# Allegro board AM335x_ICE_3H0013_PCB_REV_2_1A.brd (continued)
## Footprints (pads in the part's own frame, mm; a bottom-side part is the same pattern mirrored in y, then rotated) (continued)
CNRAPC722
  round 4.191 hole 3.556: 1(0,0)
  round 3.683 hole 3.048: 2(4.801,-2.997) 3(0,-6.248)
CNRJ45-1X1WLED
  round 3.2 hole 3.2 unplated: (-1.27,-6.35) (10.16,-6.35)
  rect 1.525x1.525 hole 0.89: 1(0,0)
  round 1.525 hole 0.89: 2(1.27,2.54) 3(2.54,0) 4(3.81,2.54) 5(5.08,0) 6(6.35,2.54) 7(7.62,0) 8(8.89,2.54)
  round 1.655 hole 1.02: 9(11.17,-8.89) 10(11.17,-10.92) 11(-2.28,-8.89) 12(-2.28,-10.92)
  round 2.337 hole 1.702: 13(-3.43,-3.3) 14(12.32,-3.3)
CON14_P5MM_3P75X9P5SMD
  rect 1.016x1.016 smd: (-1.025,-4.475) (-1.025,4.475)
  rect 0.95x0.305 smd: 1(1.675,3.25) 2(1.675,2.75) 3(1.675,2.25) 4(1.675,1.75) 5(1.675,1.25) 6(1.675,0.75) 7(1.675,0.25) 8(1.675,-0.25) 9(1.675,-0.75) 10(1.675,-1.25) 11(1.675,-1.75) 12(1.675,-2.25) 13(1.675,-2.75) 14(1.675,-3.25)
CONN_OSTTC02
  round 1.778 hole 1.27: 1(0,0) 2(5.08,0)
DA2304
  rect 1.7x1.6 smd: 1(-5.4,3) 2(-5.4,1) 3(-5.4,-1) 4(-5.4,-3) 5(5.4,-3) 6(5.4,-1) 7(5.4,1) 8(5.4,3)
DBV5
  rect 0.635x1.27 smd: 1(-0.95,-1.25) 2(0,-1.25) 3(0.95,-1.25) 4(0.95,1.25) 5(-0.95,1.25)
DCK5
  rect 0.46x0.66 smd: 1(-0.65,-0.991) 2(0,-0.991) 3(0.65,-0.991) 4(0.65,0.991) 5(-0.65,0.991)
DO157LS_116X220SMA
  rect 2.5x1.75 smd: 1(-2,0) 2(2,0)
DRCPSO_10PIN
  rect 0.8x0.25 smd: 1(-1.5,1) 2(-1.5,0.5) 3(-1.5,0) 4(-1.5,-0.5) 5(-1.5,-1) 6(1.5,-1) 7(1.5,-0.5) 8(1.5,0) 9(1.5,0.5) 10(1.5,1)
  custom 0.412x0.412 smd: 11(0,0)
EXB-2HV330JV
  rect 0.305x0.711 smd: 1(-1.75,-0.8) 2(-1.25,-0.8) 3(-0.75,-0.8) 4(-0.25,-0.8) 5(0.25,-0.8) 6(0.75,-0.8) 7(1.25,-0.8) 8(1.75,-0.8) 9(1.75,0.8) 10(1.25,0.8) 11(0.75,0.8) 12(0.25,0.8) 13(-0.25,0.8) 14(-0.75,0.8) 15(-1.25,0.8) 16(-1.75,0.8)
HDR2X9VER_335M
  rect 1.524x1.524 hole 0.889: 1(0,0)
  round 1.524 hole 0.889: 2(0,2.54) 3(2.54,0) 4(2.54,2.54) 5(5.08,0) 6(5.08,2.54) 7(7.62,0) 8(7.62,2.54) 9(10.16,0) 10(10.16,2.54) 11(12.7,0) 12(12.7,2.54) 13(15.24,0) 14(15.24,2.54) 15(17.78,0) 16(17.78,2.54) 17(20.32,0) 18(20.32,2.54)
HDR2X15-344M
  rect 1.655x1.655 hole 1.02: 1(0,0)
  round 1.655 hole 1.02: 2(0,2.54) 3(2.54,0) 4(2.54,2.54) 5(5.08,0) 6(5.08,2.54) 7(7.62,0) 8(7.62,2.54) 9(10.16,0) 10(10.16,2.54) 11(12.7,0) 12(12.7,2.54) 13(15.24,0) 14(15.24,2.54) 15(17.78,0) 16(17.78,2.54) 17(20.32,0) 18(20.32,2.54) 19(22.86,0) 20(22.86,2.54) 21(25.4,0) 22(25.4,2.54) 23(27.94,0) 24(27.94,2.54) 25(30.48,0) 26(30.48,2.54) 27(33.02,0) 28(33.02,2.54) 29(35.56,0) 30(35.56,2.54)
HDR2X20-335M
  rect 1.524x1.524 hole 0.889: 1(0,0)
  round 1.524 hole 0.889: 2(0,2.54) 3(2.54,0) 4(2.54,2.54) 5(5.08,0) 6(5.08,2.54) 7(7.62,0) 8(7.62,2.54) 9(10.16,0) 10(10.16,2.54) 11(12.7,0) 12(12.7,2.54) 13(15.24,0) 14(15.24,2.54) 15(17.78,0) 16(17.78,2.54) 17(20.32,0) 18(20.32,2.54) 19(22.86,0) 20(22.86,2.54) 21(25.4,0) 22(25.4,2.54) 23(27.94,0) 24(27.94,2.54) 25(30.48,0) 26(30.48,2.54) 27(33.02,0) 28(33.02,2.54) 29(35.56,0) 30(35.56,2.54) 31(38.1,0) 32(38.1,2.54) 33(40.64,0) 34(40.64,2.54) 35(43.18,0) 36(43.18,2.54) 37(45.72,0) 38(45.72,2.54) 39(48.26,0) 40(48.26,2.54)
HEADER10X2
  rect 0.711x2.87 smd: 1(-5.715,-2.705) 2(-5.715,2.705) 3(-4.445,-2.705) 4(-4.445,2.705) 5(-3.175,-2.705) 6(-3.175,2.705) 7(-1.905,-2.705) 8(-1.905,2.705) 9(-0.635,-2.705) 10(-0.635,2.705) 11(0.635,-2.705) 12(0.635,2.705) 13(1.905,-2.705) 14(1.905,2.705) 15(3.175,-2.705) 16(3.175,2.705) 17(4.445,-2.705) 18(4.445,2.705) 19(5.715,-2.705) 20(5.715,2.705)
HEADER_3X1
  rect 1.651x1.651 hole 1.016: 1(0,0)
  round 1.651 hole 1.016: 2(2.54,0) 3(5.08,0)
HTQFP_48PIN
  rect 1.45x0.3 smd: 1(-4.2,2.75) 2(-4.2,2.25) 3(-4.2,1.75) 4(-4.2,1.25) 5(-4.2,0.75) 6(-4.2,0.25) 7(-4.2,-0.25) 8(-4.2,-0.75) 9(-4.2,-1.25) 10(-4.2,-1.75) 11(-4.2,-2.25) 12(-4.2,-2.75) 25(4.2,-2.75) 26(4.2,-2.25) 27(4.2,-1.75) 28(4.2,-1.25) 29(4.2,-0.75) 30(4.2,-0.25) 31(4.2,0.25) 32(4.2,0.75) 33(4.2,1.25) 34(4.2,1.75) 35(4.2,2.25) 36(4.2,2.75)
  rect 0.3x1.45 smd: 13(-2.75,-4.2) 14(-2.25,-4.2) 15(-1.75,-4.2) 16(-1.25,-4.2) 17(-0.75,-4.2) 18(-0.25,-4.2) 19(0.25,-4.2) 20(0.75,-4.2) 21(1.25,-4.2) 22(1.75,-4.2) 23(2.25,-4.2) 24(2.75,-4.2) 37(2.75,4.2) 38(2.25,4.2) 39(1.75,4.2) 40(1.25,4.2) 41(0.75,4.2) 42(0.25,4.2) 43(-0.25,4.2) 44(-0.75,4.2) 45(-1.25,4.2) 46(-1.75,4.2) 47(-2.25,4.2) 48(-2.75,4.2)
  rect 4.45x4.45 smd: 49(0,0)
IND108SMD_110X102
  rect 0.711x1.194 smd: 1(-1.372,0) 2(1.372,0)
IND_354SMD_400SQ
  rect 1.702x3.607 smd: 1(-4.496,0)
  rect 1.778x3.81 smd: 2(4.496,0)
LED-SM1210
  rect 1.5x1 smd: 1(-1.75,0.7) 2(-1.75,-0.7) 3(1.75,0.7) 4(1.75,-0.7)
LEDLTST-S220
  rect 0.8x0.75 smd: 1(-1.05,0) 2(1.05,0)
LQFP64_10X10
  rect 1.651x0.305 smd: 1(-5.6,3.75) 2(-5.6,3.25) 3(-5.6,2.75) 4(-5.6,2.25) 5(-5.6,1.75) 6(-5.6,1.25) 7(-5.6,0.75) 8(-5.6,0.25) 9(-5.6,-0.25) 10(-5.6,-0.75) 11(-5.6,-1.25) 12(-5.6,-1.75) 13(-5.6,-2.25) 14(-5.6,-2.75) 15(-5.6,-3.25) 16(-5.6,-3.75) 33(5.6,-3.75) 34(5.6,-3.25) 35(5.6,-2.75) 36(5.6,-2.25) 37(5.6,-1.75) 38(5.6,-1.25) 39(5.6,-0.75) 40(5.6,-0.25) 41(5.6,0.25) 42(5.6,0.75) 43(5.6,1.25) 44(5.6,1.75) 45(5.6,2.25) 46(5.6,2.75) 47(5.6,3.25) 48(5.6,3.75)
  rect 0.305x1.651 smd: 17(-3.75,-5.6) 18(-3.25,-5.6) 19(-2.75,-5.6) 20(-2.25,-5.6) 21(-1.75,-5.6) 22(-1.25,-5.6) 23(-0.75,-5.6) 24(-0.25,-5.6) 25(0.25,-5.6) 26(0.75,-5.6) 27(1.25,-5.6) 28(1.75,-5.6) 29(2.25,-5.6) 30(2.75,-5.6) 31(3.25,-5.6) 32(3.75,-5.6) 49(3.75,5.6) 50(3.25,5.6) 51(2.75,5.6) 52(2.25,5.6) 53(1.75,5.6) 54(1.25,5.6) 55(0.75,5.6) 56(0.25,5.6) 57(-0.25,5.6) 58(-0.75,5.6) 59(-1.25,5.6) 60(-1.75,5.6) 61(-2.25,5.6) 62(-2.75,5.6) 63(-3.25,5.6) 64(-3.75,5.6)
MBR0520L
  rect 0.914x1.219 smd: 1(1.651,0) 2(-1.651,0)
MBRS140T
  rect 2.007x2.489 smd: 1(-2.045,0) 2(2.045,0)
MC-306
  rect 1.3x1.9 smd: 1(-2.75,-1.6) 2(2.75,-1.6) 3(2.75,1.6) 4(-2.75,1.6)
MH163X138PL
  round 4.14 hole 3.505: 1(0,0)
MSOP3X3-8-43M
  rect 1.35x0.4 smd: 1(-2.225,0.975) 2(-2.225,0.325) 3(-2.225,-0.325) 4(-2.225,-0.975) 5(2.225,-0.975) 6(2.225,-0.325) 7(2.225,0.325) 8(2.225,0.975)
NORCOMP_DB9F_SMD
  round 2.007 hole 1.499 unplated: (-7.95,-0.66) (7.95,-0.66)
  rect 0.8x3.5 smd: 1(-5.537,0) 2(-2.769,0) 3(0,0) 4(2.769,0) 5(5.537,0) 6(-4.153,0) 7(-1.384,0) 8(1.384,0) 9(4.153,0)
  round 4.572 hole 3.048: 10(-12.497,-0.66) 11(12.497,-0.66)
PW8
  rect 0.406x1.778 smd: 1(-0.975,-2.667) 2(-0.325,-2.667) 3(0.325,-2.667) 4(0.975,-2.667) 5(0.975,2.667) 6(0.325,2.667) 7(-0.325,2.667) 8(-0.975,2.667)
QFN4X3P5-16-39M
  rect 0.25x0.8 smd: 1(-0.75,2) 8(-0.75,-2) 9(0.75,-2) 16(0.75,2)
  rect 0.8x0.25 smd: 2(-1.75,1.25) 3(-1.75,0.75) 4(-1.75,0.25) 5(-1.75,-0.25) 6(-1.75,-0.75) 7(-1.75,-1.25) 10(1.75,-1.25) 11(1.75,-0.75) 12(1.75,-0.25) 13(1.75,0.25) 14(1.75,0.75) 15(1.75,1.25)
  rect 2.15x2.65 smd: 17(0,0)
SC70-5
  rect 0.406x0.762 smd: 1(-0.648,-0.953) 2(0,-0.953) 3(0.648,-0.953) 4(0.648,0.953) 5(-0.648,0.953)
SC70-5-43M
  rect 0.95x0.4 smd: 1(-1.075,0.65) 2(-1.075,0) 3(-1.075,-0.65) 4(1.075,-0.65) 5(1.075,0.65)
SD-MICRO-SCHA5B0300
  rect 0.914x0.457 smd: 1(-7.257,0) 2(-7.257,-0.7) 3(-7.257,-1.4) 4(-7.257,-2.1) 5(7.257,-2.1) 6(7.257,-1.4) 7(7.257,-0.7) 8(7.257,0)
  rect 0.508x0.889 smd: 9(3.775,9.989) 10(-5.975,9.989)
  rect 0.889x2.007 smd: 11(-7.25,7.635) 12(7.25,6.335)
  rect 1.118x1.524 smd: 13(-7.196,-3.365) 14(7.196,-3.365)
  rect 1.194x1.092 smd: 15(-3.425,10.488) 16(2.575,10.488)
SIP2_50LS
  round 1.016 hole 0.711: 1(0,0) 2(0,-1.27)
SIP3_50LS
  round 1.016 hole 0.711: 1(0,0) 2(0,-1.27) 3(0,-2.54)
SM-7351-CAP-0402
  round 0.635 smd: 1(-0.508,0) 2(0.508,0)
SM-7351-CAP-0603
  rect 1.092x1.041 smd: 1(-0.85,0) 2(0.85,0)
SM-7351-CAP-0805
  rect 1.346x1.524 smd: 1(-1,0) 2(1,0)
SM-7351-CAP-1206
  rect 1.2x1.85 smd: 1(1.6,0) 2(-1.6,0)
SM-7351-IND-0805
  rect 1.397x1.549 smd: 1(-0.95,0) 2(0.95,0)
SM-7351-RES-0402
  round 0.635 smd: 1(-0.508,0) 2(0.508,0)
SM-7351-RES-0603
  rect 1.143x1.092 smd: 1(-0.9,0) 2(0.9,0)
SM-SO-SC70-5
  rect 0.406x1.016 smd: 1(-0.65,-0.95) 2(0,-0.95) 3(0.65,-0.95) 4(0.65,0.95) 5(-0.65,0.95)
SM_LED_0805
  rect 1.15x1.194 smd: 1(1.125,0) 2(-1.125,0)
SM_OSC_ABM3
  rect 1.9x2.4 smd: 1(-2.05,0) 2(2.05,0)
SM_RES_LVK12
  rect 1.75x1.1 smd: 1(-1.375,0.7) 2(1.375,0.7) 3(-1.375,-0.7) 4(1.375,-0.7)
SMCJ36CA
  rect 2.6x3.2 smd: 1(-3.6,0) 2(3.6,0)
SMD0201
  rect 0.3x0.3 smd: 1(-0.3,0) 2(0.3,0)
SMD_MELF0102
  rect 1x1.2 smd: 1(-1,0) 2(1,0)
SMDFUSEBLK
  rect 4.242x3.81 smd: 1(-3.175,0) 2(3.175,0)
SMDSC70-5
  rect 0.406x1.016 smd: 1(-0.65,-0.95) 2(0,-0.95) 3(0.65,-0.95) 4(0.65,0.95) 5(-0.65,0.95)
SMINI6-F3-B
  rect 0.305x0.95 smd: 1(0.65,0.75) 2(0,0.75) 3(-0.65,0.75) 4(-0.65,-0.75) 5(0,-0.75) 6(0.65,-0.75)
SO8_W_DUB
  rect 0.61x2.184 smd: 1(-1.905,-4.445)
  oval 0.61x2.184 smd: 2(0.635,-4.445) 3(3.175,-4.445) 4(5.715,-4.445) 5(5.715,4.445) 6(3.175,4.445) 7(0.635,4.445) 8(-1.905,4.445)
SOIC8_208
  rect 0.635x1.905 smd: 1(-1.905,-3.683) 2(-0.635,-3.683) 3(0.635,-3.683) 4(1.905,-3.683) 5(1.905,3.683) 6(0.635,3.683) 7(-0.635,3.683) 8(-1.905,3.683)
SOIC8_265
  rect 2.032x0.635 smd: 1(-3.365,1.905) 2(-3.365,0.635) 3(-3.365,-0.635) 4(-3.365,-1.905) 5(3.365,-1.905) 6(3.365,-0.635) 7(3.365,0.635) 8(3.365,1.905)
SOIC-8
  rect 0.6x2 smd: 1(-1.905,-2.4) 2(-0.635,-2.4) 3(0.635,-2.4) 4(1.905,-2.4) 5(1.905,2.4) 6(0.635,2.4) 7(-0.635,2.4) 8(-1.905,2.4)
SOIC_8
  rect 0.61x2.184 smd: 1(-1.905,-2.603)
  oval 0.61x2.184 smd: 2(-0.635,-2.603) 3(0.635,-2.603) 4(1.905,-2.603) 5(1.905,2.603) 6(0.635,2.603) 7(-0.635,2.603) 8(-1.905,2.603)
SOT23-6
  rect 0.635x1.016 smd: 1(-0.953,-1.295) 2(0,-1.295) 3(0.953,-1.295) 4(0.953,1.295) 5(0,1.295) 6(-0.953,1.295)
SOT223_6PIN
  rect 0.65x1.95 smd: 1(-2.54,-3) 2(-1.27,-3) 3(0,-3) 4(1.27,-3) 5(2.54,-3)
  rect 3.2x1.95 smd: 6(0,3)
SW3_4X2P5
  rect 0.787x1.702 smd: 1(-1.7,0) 2(1.7,0)
  rect 0.787x1.092 smd: 3(0,-1.65)
SW-ND3FR10
  rect 0.711x1.702 smd: 1(-2.54,4.651) 2(2.54,4.651) 4(-2.54,-4.651) 8(2.54,-4.651) C1(0,4.651) C2(0,-4.651)
TFBGA48
  round 0.356 smd: A1(-2,2.8) A2(-1.2,2.8) A3(-0.4,2.8) A4(0.4,2.8) A5(1.2,2.8) A6(2,2.8) B1(-2,2) B2(-1.2,2) B3(-0.4,2) B4(0.4,2) B5(1.2,2) B6(2,2) C1(-2,1.2) C2(-1.2,1.2) C3(-0.4,1.2) C4(0.4,1.2) C5(1.2,1.2) C6(2,1.2) D1(-2,0.4) D2(-1.2,0.4) D3(-0.4,0.4) D4(0.4,0.4) D5(1.2,0.4) D6(2,0.4) E1(-2,-0.4) E2(-1.2,-0.4) E3(-0.4,-0.4) E4(0.4,-0.4) E5(1.2,-0.4) E6(2,-0.4) F1(-2,-1.2) F2(-1.2,-1.2) F3(-0.4,-1.2) F4(0.4,-1.2) F5(1.2,-1.2) F6(2,-1.2) G1(-2,-2) G2(-1.2,-2) G3(-0.4,-2) G4(0.4,-2) G5(1.2,-2) G6(2,-2) H1(-2,-2.8) H2(-1.2,-2.8) H3(-0.4,-2.8) H4(0.4,-2.8) H5(1.2,-2.8) H6(2,-2.8)
TH_TP_5002
  round 1.778 hole 1.016: 1(0,0)
TP60C_SMD
  round 1.27 smd: 1(0,0)
TP_SMD1MMCIRCLE
  round 1.016 smd: 1(0,0)
TSSOP4X6-20
  rect 0.4x1.6 smd: 1(-2.925,-2.9) 2(-2.275,-2.9) 3(-1.625,-2.9) 4(-0.975,-2.9) 5(-0.325,-2.9) 6(0.325,-2.9) 7(0.975,-2.9) 8(1.625,-2.9) 9(2.275,-2.9) 10(2.925,-2.9) 11(2.925,2.9) 12(2.275,2.9) 13(1.625,2.9) 14(0.975,2.9) 15(0.325,2.9) 16(-0.325,2.9) 17(-0.975,2.9) 18(-1.625,2.9) 19(-2.275,2.9) 20(-2.925,2.9)
TSSOP5X4-14-47M
  rect 1.4x0.4 smd: 1(-2.95,1.95) 2(-2.95,1.3) 3(-2.95,0.65) 4(-2.95,0) 5(-2.95,-0.65) 6(-2.95,-1.3) 7(-2.95,-1.95) 8(2.95,-1.95) 9(2.95,-1.3) 10(2.95,-0.65) 11(2.95,0) 12(2.95,0.65) 13(2.95,1.3) 14(2.95,1.95)
TVSOP-48
  rect 0.254x1.651 smd: 1(-4.6,-2.794) 2(-4.2,-2.794) 3(-3.8,-2.794) 4(-3.4,-2.794) 5(-3,-2.794) 6(-2.6,-2.794) 7(-2.2,-2.794) 8(-1.8,-2.794) 9(-1.4,-2.794) 10(-1,-2.794) 11(-0.6,-2.794) 12(-0.2,-2.794) 13(0.2,-2.794) 14(0.6,-2.794) 15(1,-2.794) 16(1.4,-2.794) 17(1.8,-2.794) 18(2.2,-2.794) 19(2.6,-2.794) 20(3,-2.794) 21(3.4,-2.794) 22(3.8,-2.794) 23(4.2,-2.794) 24(4.6,-2.794) 25(4.6,2.794) 26(4.2,2.794) 27(3.8,2.794) 28(3.4,2.794) 29(3,2.794) 30(2.6,2.794) 31(2.2,2.794) 32(1.8,2.794) 33(1.4,2.794) 34(1,2.794) 35(0.6,2.794) 36(0.2,2.794) 37(-0.2,2.794) 38(-0.6,2.794) 39(-1,2.794) 40(-1.4,2.794) 41(-1.8,2.794) 42(-2.2,2.794) 43(-2.6,2.794) 44(-3,2.794) 45(-3.4,2.794) 46(-3.8,2.794) 47(-4.2,2.794) 48(-4.6,2.794)
U_6_DRY
  rect 0.305x0.508 smd: 1(-0.5,-0.439) 2(0,-0.439) 3(0.5,-0.439) 4(0.5,0.439) 5(0,0.439) 6(-0.5,0.439)
U_8_DCU
  rect 0.254x1.27 smd: 1(-0.749,-1.473) 2(-0.249,-1.473) 3(0.249,-1.473) 4(0.749,-1.473) 5(0.749,1.473) 6(0.249,1.473) 7(-0.249,1.473) 8(-0.749,1.473)
U_10_RSE
  rect 0.3x0.58 smd: 1(-0.75,-0.635) 2(-0.25,-0.635) 3(0.25,-0.635) 4(0.75,-0.635) 6(0.75,0.635) 7(0.25,0.635) 8(-0.25,0.635) 9(-0.75,0.635)
  rect 0.63x0.35 smd: 5(0.86,0) 10(-0.86,0)
U_16_D
  rect 0.6x2 smd: 1(-4.445,-2.4) 2(-3.175,-2.4) 3(-1.905,-2.4) 4(-0.635,-2.4) 5(0.635,-2.4) 6(1.905,-2.4) 7(3.175,-2.4) 8(4.445,-2.4) 9(4.445,2.4) 10(3.175,2.4) 11(1.905,2.4) 12(0.635,2.4) 13(-0.635,2.4) 14(-1.905,2.4) 15(-3.175,2.4) 16(-4.445,2.4)
U_16_DW
  rect 0.6x2 smd: 1(-4.445,-4.7) 2(-3.175,-4.7) 3(-1.905,-4.7) 4(-0.635,-4.7) 5(0.635,-4.7) 6(1.905,-4.7) 7(3.175,-4.7) 8(4.445,-4.7) 9(4.445,4.7) 10(3.175,4.7) 11(1.905,4.7) 12(0.635,4.7) 13(-0.635,4.7) 14(-1.905,4.7) 15(-3.175,4.7) 16(-4.445,4.7)
U_28_PWP
  rect 0.3x1.45 smd: 1(-4.225,-2.8) 2(-3.575,-2.8) 3(-2.925,-2.8) 4(-2.275,-2.8) 5(-1.625,-2.8) 6(-0.975,-2.8) 7(-0.325,-2.8) 8(0.325,-2.8) 9(0.975,-2.8) 10(1.625,-2.8) 11(2.275,-2.8) 12(2.925,-2.8) 13(3.575,-2.8) 14(4.225,-2.8) 15(4.225,2.8) 16(3.575,2.8) 17(2.925,2.8) 18(2.275,2.8) 19(1.625,2.8) 20(0.975,2.8) 21(0.325,2.8) 22(-0.325,2.8) 23(-0.975,2.8) 24(-1.625,2.8) 25(-2.275,2.8) 26(-2.925,2.8) 27(-3.575,2.8) 28(-4.225,2.8)
  rect 9.7x3.4 smd: TH_PD(0,0)
U_48_RSL
  rect 0.85x0.2 smd: 1(-2.975,2.2) 2(-2.975,1.8) 3(-2.975,1.4) 4(-2.975,1) 5(-2.975,0.6) 6(-2.975,0.2) 7(-2.975,-0.2) 8(-2.975,-0.6) 9(-2.975,-1) 10(-2.975,-1.4) 11(-2.975,-1.8) 12(-2.975,-2.2) 25(2.975,-2.2) 26(2.975,-1.8) 27(2.975,-1.4) 28(2.975,-1) 29(2.975,-0.6) 30(2.975,-0.2) 31(2.975,0.2) 32(2.975,0.6) 33(2.975,1) 34(2.975,1.4) 35(2.975,1.8) 36(2.975,2.2)
  rect 0.2x0.85 smd: 13(-2.2,-2.975) 14(-1.8,-2.975) 15(-1.4,-2.975) 16(-1,-2.975) 17(-0.6,-2.975) 18(-0.2,-2.975) 19(0.2,-2.975) 20(0.6,-2.975) 21(1,-2.975) 22(1.4,-2.975) 23(1.8,-2.975) 24(2.2,-2.975) 37(2.2,2.975) 38(1.8,2.975) 39(1.4,2.975) 40(1,2.975) 41(0.6,2.975) 42(0.2,2.975) 43(-0.2,2.975) 44(-0.6,2.975) 45(-1,2.975) 46(-1.4,2.975) 47(-1.8,2.975) 48(-2.2,2.975)
  rect 4.05x4.05 smd: PPAD(-0.225,0.225)
unnamed#2
  round 1.016 smd: 1(0,0)
VLCF5020T
  custom 0.525x0.525 smd: 1(-1.7,0) 2(1.7,0)
XTAL4_3P2X2P5_SMD
  rect 1.397x1.143 smd: 1(-1.1,-0.8) 2(1.1,-0.8) 3(1.1,0.8) 4(-1.1,0.8)
XTAL4_3P2X5SMD
  rect 1.6x1.27 smd: 1(-1.854,-1.105) 2(1.854,-1.105) 3(1.854,1.105) 4(-1.854,1.105)
ZX62-AB-5PA
  rect 1.9x1.9 smd: (-1.2,-2.675) (1.2,-2.675)
  rect 0.4x1.35 smd: 1(-1.3,0) 2(-0.65,0) 3(0,0) 4(0.65,0) 5(1.3,0)
  rect 2.1x1.6 smd: S1(-3.1,-0.125) S2(3.1,-0.125)
  rect 1.8x1.9 smd: S3(-4.1,-2.675) S4(4.1,-2.675)

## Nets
AGND_CAN: J9.10 J9.11 R175.1(P1)
AGND_PRUETH0: C2.2 C5.2 R242.1(P1) U3.15(AGND#15) U3.19(AGND#19)
AGND_PRUETH1: C1.2 C3.2 R239.1(P1) U2.15(AGND#15) U2.19(AGND#19)
AGNDFRAME_PRUETH0: J2.13(SHLD1) J2.14(SHLD2) R91.1(P1)
AGNDFRAME_PRUETH1: J1.13(SHLD1) J1.14(SHLD2) R96.1(P1)
DGND: C4.2 C6.2 C7.2 C8.2 C9.2 C10.2 C11.2 C12.2 C13.2 C14.2 C15.2 C16.2 C17.2 C18.2 C19.2 C20.2 C21.2 C22.2 C23.2 C25.2 C26.2 C27.2 C28.2 C29.2 C30.2 C31.2 C32.2 C37.2 C38.2 C39.2 C41.2 C43.2 C44.2 C45.2 C46.2 C47.2 C48.2 C49.2 C50.2 C51.2 C52.2 C53.2 C54.2 C55.2 C57.2 C58.2 C59.2 C60.2 C61.2 C62.2 C63.2 C64.2 C65.2 C66.2 C67.2 C68.2 C69.2 C70.2 C71.2 C72.2 C73.2 C74.2 C75.2 C76.2 C77.2 C78.2 C79.2 C80.2 C81.2 C82.2 C83.2 C84.2 C85.2 C86.2 C87.2 C88.2 C89.1 C90.1 C91.2 C92.2 C93.2 C94.2 C97.2 C101.2 C102.2 C103.2 C104.2 C105.2 C108.2 C109.1 C110.1 C111.1 C112.2 C113.2 C114.2 C115.2 C116.2 C117.2 C118.2 C119.1 C120.2 C121.1 C122.2 C123.2 C124.2 C125.2 C126.2 C127.2 C128.2 C129.2 C130.2 C131.2 C132.2 C133.2 C134.2 C135.2 C136.2 C137.1 C138.2 C139.2 C140.2 C141.2 C142.2 C143.1 C144.2 C145.2 C146.2 C147.2 C148.2 C149.2 C150.2 C151.2 C152.2 C153.2 C154.2 C155.2 C156.2 C157.1 C158.2 C159.2 C160.1 C161.2 C163.2 C164.2 C165.2 C166.2 C167.2 C168.2 C169.2 C170.2 C171.2 C172.1 C173.1 C174.2 C175.1 C176.2 C177.2 C178.2 C179.1 C180.2 C181.2 C182.2 C183.2 C184.2 C186.2 C187.2 C188.2 C189.2 C190.2 C192.2 C193.2 C194.2 C195.2 C196.2 C197.2 C198.2 C199.2 C200.2 C201.2 C202.1 C203.2 C204.2 C205.2 C206.1 C207.2 C208.1 C209.2 C210.2 C211.1 C212.2 C213.1 C214.2 C215.2 C216.2 C217.2 C218.2 C219.2 C220.2 C221.1 C222.1 C223.2 C224.2 C225.1 C226.2 C227.2 C228.2 C229.1 C230.2 C231.2 C232.1 C233.2 C234.2 C235.2 C236.2 C237.2 C238.2 C239.2 C240.2 C241.2 C242.2 C243.2 C244.2 C245.2 C246.2 C247.2 C248.2 C249.2 C250.2 C251.2 C252.2 C253.2 C254.2 C256.2 C257.2 C258.2 C259.2 C260.2 C261.2 C262.2 C263.2 C264.2 C265.2 C266.2 C267.2 C268.2 C269.2 C272.2 C273.2 C275.2 C277.2 D16.1(CATHODE) D17.2(ANODE) D19.2(ANODE) FB11.2 FB13.1 J1.8 J2.8 J3.2 J3.15 J11.2 J11.3 J12.2 J13.5(GND) J14.17 J14.18 J14.29 J14.30 J15.8(GND#8) J15.10(GND#10) J15.12(GND#12) J15.16(GND#16) J15.20(GND#20) J16.6(VSS) J16.9(GND) J17.8 MH1.1 MH2.1 MH3.1 MH4.1 Q1.1(4) Q1.4 Q2.1(4) Q2.4 Q3.1(4) Q3.4 Q4.1(4) R9.1(P1) R10.1(P1) R14.1(P1) R17.1(P1) R38.1(P1) R40.1(P1) R41.1(P1) R62.1 R65.2(P2) R66.1 R82.1(P1) R87.1(P1) R88.1(P1) R91.2(P2) R96.2(P2) R99.1(P1) R100.1(P1) R102.1(P1) R103.1(P1) R104.1(P1) R106.1(P1) R107.1(P1) R108.1(P1) R109.1(P1) R110.1(P1) R113.1(P1) R115.1(P1) R127.1(P1) R137.1(P1) R157.1(P1) R158.1(P1) R159.1(P1) R160.1(P1) R161.1(P1) R162.1(P1) R163.1(P1) R164.1(P1) R165.1(P1) R166.1(P1) R167.1(P1) R168.1(P1) R169.1(P1) R170.1(P1) R171.1(P1) R174.1(P1) R176.1(P1) R178.1 R183.1 R185.1(P1) R187.1(P1) R188.1 R193.1 R195.1 R221.1(P1) R222.1(P1) R223.1(P1) R229.2(P2) R232.2 R239.2(P2) R242.2(P2) R244.2(P2) R277.1(P1) R278.1(P1) S1.1(A1) TP18.1 TP19.1 U1.H1(VSS1) U1.H6(VSS2) U2.35(IOGND#35) U2.36(DGND) U2.47(IOGND#47) U2.49(GNDPAD) U3.35(IOGND#35) U3.36(DGND) U3.47(IOGND#47) U3.49(GNDPAD) U4.4(GND) U5.3(GND) U6.1(A0) U6.2(A1) U6.3(A2) U6.4(VSS) U7.3(GND) U8.3(GND) U9.8(GND) U9.13(4B2) U9.14(4B1) U9.17(EPAD) U10.3(GND) U11.8(GND) U11.17(EPAD) U12.5(GND1) U12.10(GND2) U13.4(GND) U14.A1(VSS#A1) U14.A18(VSS#A18) U14.F8(VSS#F8) U14.G8(VSS#G8) U14.G9(VSS#G9) U14.G11(VSS#G11) U14.G12(VSS#G12) U14.H6(VSS#H6) U14.H7(VSS#H7) U14.H8(VSS#H8) U14.H9(VSS#H9) U14.H10(VSS#H10) U14.H12(VSS#H12) U14.J6(VSS#J6) U14.J7(VSS#J7) U14.J8(VSS#J8) U14.J9(VSS#J9) U14.J10(VSS#J10) U14.J11(VSS#J11) U14.K7(VSS#K7) U14.K9(VSS#K9) U14.K10(VSS#K10) U14.K11(VSS#K11) U14.L10(VSS#L10) U14.L11(VSS#L11) U14.L12(VSS#L12) U14.L13(VSS#L13) U14.M6(VSS#M6) U14.M7(VSS#M7) U14.M8(VSS#M8) U14.M9(VSS#M9) U14.M10(VSS#M10) U14.M12(VSS#M12) U14.M14(VSSA_USB#M14) U14.N7(VSS#N7) U14.N10(VSS#N10) U14.N11(VSS#N11) U14.N14(VSSA_USB#N14) U14.V1(VSS#V1) U14.V18(VSS#V18) U15.A9(VSS1) U15.B1(VSSQ1) U15.B3(VSS2) U15.B9(VSSQ2) U15.D1(VSSQ3) U15.D8(VSSQ4) U15.E1(VSS3) U15.E2(VSSQ5) U15.E8(VSSQ6) U15.F9(VSSQ7) U15.G1(VSSQ8) U15.G8(VSS4) U15.G9(VSSQ9) U15.J2(VSS5) U15.J8(VSS6) U15.M1(VSS7) U15.M9(VSS8) U15.P1(VSS9) U15.P9(VSS10) U15.T1(VSS11) U15.T9(VSS12) U16.4(GND1) U17.4(GND) U18.1(GND.1) U18.5(GND.2) U18.10(AGND) U18.11(GND.3) U18.13(TEST) U18.15(GND.4) U18.25(GND.5) U18.32(ACBUS5) U18.35(GND.6) U18.47(GND.7) U18.51(GND.8) U19.2(GND) U19.5(GS1) U20.3(GND) U21.6(GND) U22.15(GNDIO) U22.17(REFGND) U22.20(OSC32KIN) U22.30(VFB3) U22.34(GND1) U22.43(GND2) U22.PPAD(GNDP) U23.4(GND) U24.5(GND) U25.4(GND) U26.1(1O\E\) U26.4(GND1) U26.10(GND2) U26.15(GND3) U26.21(GND4) U26.24(2O\E\) U26.28(GND5) U26.34(GND6) U26.39(GND7) U26.45(GND8) U28.3(GND1) U29.4(PGND) U29.8(GND) U29.11(PWRPD) U30.2(GND) U31.7(A2) U31.8(G\) U31.9(A0) U31.10(A1) U31.16(GND) U32.3(GND#3) U32.6(GND#6) U33.2(GND) U34.2(GND) U35.28(GND) U35.TH_PD(THRM) U37.10(GND) U38.10(GND)
GND_EARTH: FB13.2 J13.S1 J13.S2 J13.S3 J13.S4 J16.11(GND3) J16.12(GND4) J16.13(GND5) J16.14(GND6) J16.15(GND7) J16.16(GND8) S1.3(A3)
GND_OSC0: C99.2 C100.2 C106.2 U14.V11(VSS_OSC)
GND_OSC1: C40.1 C42.1 U14.A5(VSS_RTC)
GNDA_ADC: C33.2 C34.2 C35.2 C36.2 FB11.1 J14.38 J14.39 J14.40 U14.A9(VREFN) U14.E8(VSSA_ADC)
GNDPROFI: C24.2(NEG) C95.2 C96.2 C98.2 C107.2 C185.2 C191.2(NEG) J7.2 J8.3 L1.6 L1.7 R153.1(P1) R175.2(P2) U16.5(GND2) U27.3(GND) U27.4(E\N\) U28.9(GND2#9) U28.11(GND2#11) U28.14(GND2#14) U28.15(GND2#15)
V3_3D: C7.1 C8.1 C9.1 C10.1 C11.1 C12.1 C15.1 C17.1 C18.1 C19.1 C20.1 C22.1 C44.1 C46.1 C69.1 C70.1 C75.1 C76.1 C77.1 C78.1 C79.1 C80.1 C85.1 C86.1 C87.1 C88.1 C91.1 C92.1 C93.1 C94.1 C123.1 C190.1 C207.1 C218.1 C219.1 C220.1 C230.1 C231.1 C232.2 C236.1 C238.1 C265.1 C266.1 C275.1 C277.1 FB9.1 FB10.1 FB12.1 J3.1 J15.5(TVDD) J17.7 L1.2 L1.3 R11.1 R15.2(P2) R16.2(P2) R18.2(P2) R19.2(P2) R21.2(P2) R24.2(P2) R25.2(P2) R27.2(P2) R28.2(P2) R29.2(P2) R30.2(P2) R31.2(P2) R32.2(P2) R33.2(P2) R34.2(P2) R75.2(P2) R89.2(P2) R90.2(P2) R92.2(P2) R93.2(P2) R94.2(P2) R95.2(P2) R97.2(P2) R98.2(P2) R101.2(P2) R111.2(P2) R112.1(P1) R114.1(P1) R116.1(P1) R117.1(P1) R118.1(P1) R119.1(P1) R120.1(P1) R121.1(P1) R122.1(P1) R123.1(P1) R124.2(P2) R125.2(P2) R129.2(P2) R130.2(P2) R131.2(P2) R134.2(P2) R135.2(P2) R141.2(P2) R145.2(P2) R148.2(P2) R199.2(P2) R200.2(P2) R205.2(P2) R206.2(P2) R210.2(P2) R211.2(P2) R240.2(P2) R241.2(P2) R279.1(P1) R280.1(P1) SW1.C1 SW1.C2 U1.G4(VCC) U2.32(VDD33_IO#32) U2.48(VDD33_IO#48) U3.32(VDD33_IO#32) U3.48(VDD33_IO#48) U4.8(VCC) U5.5(VCC) U6.8(VCC) U7.5(VCC) U8.5(VCC) U9.16(VCC) U10.5(VCC) U11.16(VCC) U12.6(VDDOUT1) U12.7(VDDOUT2) U16.1(VCC1) U17.8(VCC) U18.20(VCCIO.1) U18.28(ACBUS2) U18.31(VCCIO.2) U18.42(VCCIO.3) U18.56(VCCIO.4) U19.1(GS0) U19.4(VDD) U25.8(VCC) U26.7(VCC1) U26.18(VCC2) U26.31(VCC3) U26.42(VCC4) U28.4(VCC1) U31.1(VCC) U32.4(OUT) U33.6(VCC) U37.20(VCC) U38.20(VCC)
V3_3D_PROFIA: L1.4 U28.1(D1)
V3_3D_PROFIB: L1.1 U28.2(D2)
V3_3D_PRUETH0JCK: C71.1 C72.1 J2.3 J2.4 R280.2(P2)
V3_3D_PRUETH1JCK: C73.1 C74.1 J1.3 J1.4 R279.2(P2)
V5_0D: C48.1 C57.1 C58.1 C59.1 C60.1 C61.1 C64.1 C66.1 C97.1 C217.1 C226.1 C227.1 C228.1 C251.1 C257.1 FB3.2 J14.27 J14.28 L2.1 L3.2 R67.2(P2) R132.1(P1) R133.1(P1) R136.1(P1) R140.1(P1) R143.1(P1) R151.1(P1) R155.1(P1) R173.1(P1) R224.1(P1) U22.3(VCC3) U22.6(VCC6) U22.13(VCCIO) U22.23(VCC5) U22.27(VBACKUP) U22.28(VCC7) U22.36(VCC1) U22.41(VCC2) U22.47(VCC4) U30.1(IN) U30.3(EN) U32.2(IN) U34.5(VIN)
V5_0VOP: C55.1 C234.1 C240.1 U20.5(VCC) U35.15(5VOP)
V13: C62.1 C252.1 C255.1 C258.1 D20.1(CATHODE) J17.1 R220.2(P2)
V24_0HVS: C233.1 C242.1 C243.1 C248.1 C249.1 C273.1 D19.1(CATHODE) F1.2 J14.2 J14.4 J14.6 J14.8 J14.10 J14.12 J14.14 J14.16 R227.2(P2) R243.1(P1) U21.7(VIN)
V24_IN: D18.2(ANODE) J3.17 J11.1 J12.1
VBAT_LCD: C268.1 C269.1 J17.10
VDD1_SMPS: R86.1(P1) R219.1(I1)
VDD1_SMPS_AM335X: C37.1 C151.1 C170.1 C203.1 C204.1 C210.1 R219.2(I2) TP25.1(TP) U14.A2(VDD_MPU_MON) U14.F10(VDD_MPU#F10) U14.F11(VDD_MPU#F11) U14.F12(VDD_MPU#F12) U14.F13(VDD_MPU#F13) U14.G13(VDD_MPU#G13) U14.H13(VDD_MPU#H13) U14.J13(VDD_MPU#J13)
VDD2_SMPS: R73.1(P1) R212.1(I1)
VDD2_SMPS_AM335X: C130.1 C131.1 C134.1 C142.1 C149.1 C150.1 C154.1 C155.1 C163.1 C164.1 C169.1 C171.1 C178.1 C187.1 C192.1 R212.2(I2) U14.F6(VDD_CORE#F6) U14.F7(VDD_CORE#F7) U14.G6(VDD_CORE#G6) U14.G7(VDD_CORE#G7) U14.G10(VDD_CORE#G10) U14.H11(VDD_CORE#H11) U14.J12(VDD_CORE#J12) U14.K6(VDD_CORE#K6) U14.K8(VDD_CORE#K8) U14.K12(VDD_CORE#K12) U14.L6(VDD_CORE#L6) U14.L7(VDD_CORE#L7) U14.L8(VDD_CORE#L8) U14.L9(VDD_CORE#L9) U14.M11(VDD_CORE#M11) U14.M13(VDD_CORE#M13) U14.N8(VDD_CORE#N8) U14.N9(VDD_CORE#N9) U14.N12(VDD_CORE#N12) U14.N13(VDD_CORE#N13)
VDD_1V8FT: C206.2 C208.2 C224.1 C225.2 U18.12(VCORE.1) U18.37(VCORE.2) U18.49(VREGOUT) U18.64(VCORE.3)
VDD_FTREGIN: FB9.2 U18.50(VREGIN)
VDD_FTVPHY: C213.2 FB10.2 U18.4(VPHY)
VDD_FTVPLL: C221.2 FB12.2 U18.9(VPLL)
VDD_LED: C45.1 D1.1(A) D2.1(A) FB3.1 R128.2(P2)
VDD_RTC: C195.1 U14.D6(CAP_VDD_RTC)
VDDA_ADC: C36.1 FB2.1 R60.2(P2) U14.D8(VDDA_ADC)
VDDS_DDR: C25.1 C26.1 C27.1 C28.1 C30.1 C31.1 C101.1 C102.1 C103.1 C104.1 C105.1 C115.1 C117.1 C118.1 C122.1 C126.1 C127.1 C128.1 C129.1 C133.1 C136.1 C138.1 C140.1 C141.1 C144.1 C146.1 C147.1 C153.1 C156.1 C158.1 C161.1 C162.2 C165.1 C168.1 C174.1 C176.1 C180.1 C183.1 C209.1 R59.1(P1) R85.1(P1) R191.2 U14.E5(VDDS_DDR#E5) U14.F5(VDDS_DDR#F5) U14.G5(VDDS_DDR#G5) U14.H5(VDDS_DDR#H5) U14.J5(VDDS_DDR#J5) U14.K5(VDDS_DDR#K5) U14.L5(VDDS_DDR#L5) U15.A1(VDDQ1) U15.A8(VDDQ2) U15.B2(VDD1) U15.C1(VDDQ3) U15.C9(VDDQ4) U15.D2(VDDQ5) U15.D9(VDD9) U15.E9(VDDQ7) U15.F1(VDDQ8) U15.G7(VDD2) U15.H2(VDDQ9) U15.H9(VDDQ10) U15.K2(VDD4) U15.K8(VDD5) U15.N1(VDD6) U15.N9(VDD7) U15.R1(VDD8) U15.R9(VDD3) U29.2(VLDOIN)
AIN1: J14.31 U14.C7(AIN1)
AIN2: J14.33 U14.B7(AIN2)
AIN3: J14.35 U14.A7(AIN3)
AIN4: J14.37 U14.C8(AIN4)
AIN5: J14.32 U14.B8(AIN5)
AIN6: J14.34 U14.A8(AIN6)
AIN7: J14.36 U14.C9(AIN7)
AM335X_OSC0_IN: C100.1 R144.2 R172.2(P2) U14.V10(XTALIN) Y3.3
AM335X_REFCLK_RMII1: R13.2 U14.H18(MII1_REFCLK)
AM335X_REFCLK_RMII2: R12.2 U14.H16(MII1_COL)
B_PRUETH0_LINKLED: J2.10(D2) R90.1(P1) TP20.1 U3.28(LED_LINK)
BOOT: C56.1 U21.1(BOOT)
C1N: C270.2 J17.11
C1P: C270.1 J17.12
C2N: C271.2 J17.13
C2P: C271.1 J17.14
CAN0_H: J9.7 R238.1(P1) U16.7(CANH)
CAN0_L: J9.2 R238.2(P2) U16.6(CANL)
CAN0_RXDF: R186.2 U16.2(RXD)
CAN0_TXDF: C145.1 R181.2 U16.3(TXD)
CAN_GND/PROFIBUS_A: J8.2 J9.3
CAP_VBB_MPU: C199.1 U14.C10(CAP_VBB_MPU)
CAP_VDD_SRAM_CORE: C198.1 U14.D9(CAP_VDD_SRAM_CORE)
CAP_VDD_SRAM_MPU: C200.1 U14.D11(CAP_VDD_SRAM_MPU)
DDR_A0: RP2.1 U14.F3(DDR_A0) U15.N3(A0)
DDR_A1: RP2.3 U14.H1(DDR_A1) U15.P7(A1)
DDR_A2: RP3.7 U14.E4(DDR_A2) U15.P3(A2)
DDR_A3: RP3.4 U14.C3(DDR_A3) U15.N2(A3)
DDR_A4: RP2.6 U14.C2(DDR_A4) U15.P8(A4)
DDR_A5: RP3.6 U14.B1(DDR_A5) U15.P2(A5)
DDR_A6: RP1.2 U14.D5(DDR_A6) U15.R8(A6)
DDR_A7: RP1.8 U14.E2(DDR_A7) U15.R2(A7)
DDR_A8: RP1.1 U14.D4(DDR_A8) U15.T8(A8)
DDR_A9: RP1.6 U14.C1(DDR_A9) U15.R3(A9)
DDR_A10: RP1.5 U14.F4(DDR_A10) U15.L7(A10)
DDR_A11: RP1.4 U14.F2(DDR_A11) U15.R7(A11)
DDR_A12: RP2.4 U14.E3(DDR_A12) U15.N7(A12)
DDR_A13: RP1.7 U14.H3(DDR_A13) U15.T3(A13)
DDR_A14: RP1.3 U14.H4(DDR_A14) U15.T7(A14)
DDR_BA0: RP3.3 U14.C4(DDR_BA0) U15.M2(BA0)
DDR_BA1: RP2.5 U14.E1(DDR_BA1) U15.N8(BA1)
DDR_BA2: RP3.8 U14.B3(DDR_BA2) U15.M3(BA2)
DDR_CASN: RP3.5 U14.F1(DDR_CASN) U15.K3(CASN)
DDR_CKE: R178.2 U14.G3(DDR_CKE) U15.K9(CKE)
DDR_CLK: R179.1 U14.D2(DDR_CK) U15.J7(CK)
DDR_CLKN: R182.1 U14.D1(DDR_CKN) U15.K7(CKN)
DDR_CSN: RP3.1 U14.H2(DDR_CSN0) U15.L2(CSN)
DDR_D0: U14.M3(DDR_D0) U15.H7(DQ7)
DDR_D1: U14.M4(DDR_D1) U15.F8(DQ3)
DDR_D2: U14.N1(DDR_D2) U15.G2(DQ6)
DDR_D3: U14.N2(DDR_D3) U15.F2(DQ2)
DDR_D4: U14.N3(DDR_D4) U15.H3(DQ4)
DDR_D5: U14.N4(DDR_D5) U15.H8(DQ5)
DDR_D6: U14.P3(DDR_D6) U15.E3(DQ0)
DDR_D7: U14.P4(DDR_D7) U15.F7(DQ1)
DDR_D8: U14.J1(DDR_D8) U15.C3(DQ9)
DDR_D9: U14.K1(DDR_D9) U15.C2(DQ11)
DDR_D10: U14.K2(DDR_D10) U15.D7(DQ8)
DDR_D11: U14.K3(DDR_D11) U15.C8(DQ10)
DDR_D12: U14.K4(DDR_D12) U15.A3(DQ15)
DDR_D13: U14.L3(DDR_D13) U15.A2(DQ13)
DDR_D14: U14.L4(DDR_D14) U15.A7(DQ12)
DDR_D15: U14.M1(DDR_D15) U15.B8(DQ14)
DDR_DQM0: U14.M2(DDR_DQM0) U15.E7(LDM)
DDR_DQM1: U14.J2(DDR_DQM1) U15.D3(UDM)
DDR_DQS0: U14.P1(DDR_DQS0) U15.F3(LDQS)
DDR_DQS1: U14.L1(DDR_DQS1) U15.C7(UDQS)
DDR_DQSN0: U14.P2(DDR_DQSN0) U15.G3(LDQSN)
DDR_DQSN1: U14.L2(DDR_DQSN1) U15.B7(UDQSN)
DDR_ODT: RP3.2 U14.G1(DDR_ODT) U15.K1(ODT)
DDR_RASN: R180.1 U14.G4(DDR_RASN) U15.J3(RASN)
DDR_RESETN: R59.2(P2) U14.G2(DDR_RESETN) U15.T2(RESET#)
DDR_VREF: C159.1 C167.1 C188.1 TP21.1 U14.J4(DDR_VREF) U15.H1(VREF_DQ) U15.M8(VREF_CA) U29.6(REFOUT)
DDR_VTP: R185.2(P2) U14.J3(DDR_VTP)
DDR_VTT_EN: R62.2 R63.1 U14.F16(USB0_DRVVBUS) U29.7(EN)
DDR_WEN: RP2.2 U14.B2(DDR_WEN) U15.L3(WEN)
DRAIN0: D15.1(CATHODE) J14.19 U31.3(DRAIN0)
DRAIN1: D14.1(CATHODE) J14.20 U31.4(DRAIN1)
DRAIN2: D12.1(CATHODE) J14.21 U31.5(DRAIN2)
DRAIN3: D10.1(CATHODE) J14.22 U31.6(DRAIN3)
DRAIN4: D9.1(CATHODE) J14.23 U31.11(DRAIN4)
DRAIN5: D8.1(CATHODE) J14.24 U31.12(DRAIN5)
DRAIN6: D7.1(CATHODE) J14.25 U31.13(DRAIN6)
DRAIN7: D6.1(CATHODE) J14.26 U31.14(DRAIN7)
EMU2_GPIO0_19: Q2.2(5) R35.2(P2) R106.2(P2) U14.A15(XDMA_EVENT_INTR0)
EMU2R: J15.17(EMU2) R35.1(P1)
EMU3_GPIO0_20: Q3.5 R26.1(P1) R108.2(P2) U14.D14(XDMA_EVENT_INTR1)
EMU3R: J15.18(EMU3) R26.2(P2)
EMU4: J3.10 R36.2(P2) U14.A14(MCASP0_AHCLKX)
EMU4R: J15.19(EMU4) R36.1(P1)
EMU_RSTN: C13.1 J15.15(SRST) R20.1(P1)
ENZ_KALDO_1P8V: R65.1(P1) U14.B4(RTC_KALDO_ENN)
ETH0_CLKIN: R42.2 U3.34(XI)
ETH1_CLKIN: R154.2 U2.34(XI)
F_ADBUS0: R209.2(P2) U18.16(ADBUS0)
F_ADBUS1: R192.2(P2) U18.17(ADBUS1)
F_ADBUS2: R190.2(P2) U18.18(ADBUS2)
F_ADBUS3: R194.2(P2) U18.19(ADBUS3)
F_ADBUS4: R201.2(P2) U18.21(ADBUS4)
F_ADBUS5: R203.2(P2) U18.26(ACBUS0)
F_ADBUS6: R202.2(P2) U18.23(ADBUS6)
F_ADBUS7: R204.2(P2) U18.30(ACBUS4)
F_EECS: R210.1(P1) U18.63(EECS) U33.5(CS)
F_EEDATA: R207.1(P1) U18.61(EEDATA) U33.3(DIN)
F_EEDOUT: R207.2(P2) R211.1(P1) U33.1(DOUT)
F_EESK: R206.1(P1) U18.62(EESK) U33.4(SK)
FET_NOE: R11.2 U4.1(NOE1) U4.7(NOE2) U14.C18(ECAP0_IN_PWM0_OUT)
FT_REF: R193.2 U18.6(REF)
FT_RESETN: R205.1(P1) U18.14(RESET#)
FT_SRESET: R137.2(P2) R141.1(P1) R203.1(P1) U10.2(A)
GPIO2-5: R21.1(P1) U5.1(A) U14.T6(GPMC_BEN0_CLE)
GPIO2_12: U1.C3(A18) U14.T3(LCD_DATA6) U37.5(2Y3)
GPIO2_13: U1.D4(A19) U14.T4(LCD_DATA7) U37.3(2Y4)
GPIO3_18: J3.9 R244.1(P1) U14.B12(MCASP0_ACLKR) U35.26(L\D\)
GPIO3_19: J3.11 U14.C13(MCASP0_FSR) U28.7(DE)
GPIO3_20: J3.13 U14.D13(MCASP0_AXR1)
GPMC_A0: J4.1 U1.E1(A0) U26.2(1Q1)
GPMC_A1: J4.3 U1.D1(A1) U26.3(1Q2)
GPMC_A2: J4.5 U1.C1(A2) U26.5(1Q3)
GPMC_A3: J4.7 U1.A1(A3) U26.6(1Q4)
GPMC_A4: J4.9 U1.B1(A4) U26.8(1Q5)
GPMC_A5: J4.11 U1.D2(A5) U26.9(1Q6)
GPMC_A6: J4.13 U1.C2(A6) U26.11(1Q7)
GPMC_A7: J4.15 U1.A2(A7) U26.12(1Q8)
GPMC_A8: J4.17 U1.B5(A8) U26.13(2Q1)
GPMC_A9: J4.19 U1.A5(A9) U26.14(2Q2)
GPMC_A10: U1.C5(A10) U26.16(2Q3)
GPMC_A11: U1.D5(A11) U26.17(2Q4)
GPMC_A12: U1.B6(A12) U26.19(2Q5)
GPMC_A13: U1.A6(A13) U26.20(2Q6)
GPMC_A14: U1.C6(A14) U26.22(2Q7)
GPMC_A15: U1.D6(A15) U26.23(2Q8)
GPMC_AD0: J4.2 U1.E2(DQ0) U14.U7(GPMC_AD0) U26.47(1D1)
GPMC_AD1: J4.4 U1.H2(DQ1) U14.V7(GPMC_AD1) U26.46(1D2)
GPMC_AD2: J4.6 U1.E3(DQ2) U14.R8(GPMC_AD2) U26.44(1D3)
GPMC_AD3: J4.8 U1.H3(DQ3) U14.T8(GPMC_AD3) U26.43(1D4)
GPMC_AD4: J4.10 U1.H4(DQ4) U14.U8(GPMC_AD4) U26.41(1D5)
GPMC_AD5: J4.12 U1.E4(DQ5) U14.V8(GPMC_AD5) U26.40(1D6)
GPMC_AD6: J4.14 U1.H5(DQ6) U14.R9(GPMC_AD6) U26.38(1D7)
GPMC_AD7: J4.16 U1.E5(DQ7) U14.T9(GPMC_AD7) U26.37(1D8)
GPMC_AD8: J4.18 U1.F2(DQ8) U14.U10(GPMC_AD8) U26.36(2D1)
GPMC_AD9: J4.20 U1.G2(DQ9) U14.T10(GPMC_AD9) U26.35(2D2)
GPMC_AD10: J4.22 U1.F3(DQ10) U14.T11(GPMC_AD10) U26.33(2D3)
GPMC_AD11: J4.24 U1.G3(DQ11) U14.U12(GPMC_AD11) U26.32(2D4)
GPMC_AD12: J4.26 U1.F4(DQ12) U14.T12(GPMC_AD12) U26.30(2D5)
GPMC_AD13: J4.28 U1.G5(DQ13) U14.R12(GPMC_AD13) U26.29(2D6)
GPMC_AD14: J4.30 U1.F5(DQ14) U14.V13(GPMC_AD14) U26.27(2D7)
GPMC_AD15: J4.29 U1.G6(DQ15_A-1) U14.U13(GPMC_AD15) U26.26(2D8)
GPMC_ADVN_ALE: J4.27 U14.R7(GPMC_ADVN_ALE) U26.25(2CLK) U26.48(1CLK)
GPMC_CSN0: R125.1(P1) U1.F1(E\) U14.V6(GPMC_CSN0)
GPMC_CSN2: J4.21 U14.V9(GPMC_CSN2)
GPMC_NOR_A1: R102.2(P2) U1.E6(A16) U14.U5(LCD_VSYNC)
GPMC_NOR_A2: R115.2(P2) U1.B2(A17) U14.R5(LCD_HSYNC)
GPMC_OEN_REN: J4.25 U1.G1(G\) U14.T7(GPMC_OEN_REN)
GPMC_WEN: J4.23 U1.A4(W\) U14.U6(GPMC_WEN)
I2C0_SCL: J3.6 J17.5 R69.2(P2) R196.1(P1) U6.6(SCL) U12.12(S2/SCL) U14.C16(I2C0_SCL) U25.6(SCL) U31.15(SCL)
I2C0_SDA: J3.4 J17.4 R61.1(P1) R72.2(P2) U6.5(SDA) U12.13(S1/SDA) U14.C17(I2C0_SDA) U25.7(SDA) U31.2(SDA)
INDUS_INPUT0: J14.1 R226.1(P1)
INDUS_INPUT1: J14.3 R84.1(P1)
INDUS_INPUT2: J14.5 R83.1(P1)
INDUS_INPUT3: J14.7 R81.1(P1)
INDUS_INPUT4: J14.9 R80.1(P1)
INDUS_INPUT5: J14.11 R79.1(P1)
INDUS_INPUT6: J14.13 R74.1(P1)
INDUS_INPUT7: J14.15 R68.1(P1) R243.2(P2)
INDUS_INPUTSO: U20.2(A) U35.23(SOP)
IREF: J17.3 R232.1
JTAG_EMU0: J15.13(EMU0) R25.1(P1) R202.1(P1) U14.C14(EMU0///////GPIO3_7)
JTAG_EMU1: J15.14(EMU1) R24.1(P1) R204.1(P1) U14.B14(EMU1///////GPIO3_8)
JTAG_TCK: R22.2(P2) R23.2(P2) R209.1(P1) U14.A12(TCK)
JTAG_TDI: J15.3(TDI) R192.1(P1) U14.B11(TDI)
JTAG_TDO: J15.7(TDO) R190.1(P1) U14.A11(TDO)
JTAG_TMS: J15.1(TMS) R194.1(P1) U14.C11(TMS)
JTAG_TRSTN: J15.2(TRSTN) R14.2(P2) R201.1(P1) U14.B10(TRSTN)
LATCH0_IN: J3.3 U14.D18(UART1_CTSN)
LATCH1_IN: J3.5 U14.D17(UART1_RTSN)
LCD_BST_CONV_CTL: R225.2(P2) U14.F15(USB1_DRVVBUS)
LED_1: Q2.5 R107.2(P2) U14.K15(MII1_TXD2)
LED_2: Q1.2(5) R104.2(P2) R126.2(P2) U14.J18(MII1_TXD3)
LED_3: Q1.5 R103.2(P2) U14.K18(MII1_TXCLK)
LED_4: Q3.2(5) R109.2(P2) TP37.1 U14.U9(GPMC_CSN1)
MDIO_CLK: R149.2(P2) U14.M18(MDIO_CLK)
MDIO_DATA: R147.2(P2) U14.M17(MDIO_DATA)
MMC0_CLK: J16.5(CLOCK) R58.1(P1) R237.1(P1) U24.6(IO4)
MMC0_CMD: J16.3(CMD) R235.1(P1) U14.G18(MMC0_CMD) U24.3(IO3)
MMC0_DAT0: J16.7(DAT0) R236.1(P1) U14.G16(MMC0_DAT0) U24.7(IO5)
MMC0_DAT1: J16.8(DAT1) R234.1(P1) U14.G15(MMC0_DAT1) U24.8(IO6)
MMC0_DAT2: J16.1(DAT2) R231.1(P1) U14.F18(MMC0_DAT2) U24.1(IO1)
MMC0_DAT3: J16.2(CD/DAT3) R233.1(P1) U14.F17(MMC0_DAT3) U24.2(IO2)
MUX_MII_CTL1: U9.1(S) U11.1(S) U14.L18(MII1_RXCLK)
NOR_READY: R111.1(P1) U1.A3(RB\)
NOR_RP: R105.2(P2) U1.B4(R\P\)
OSC0_OUT: R156.1(P1) U14.U11(XTALOUT)
OSC0_OUT1: C99.1 R156.2(P2) R172.1(P1) Y3.1
OSC1_IN: C42.2 U14.A6(RTC_XTALIN) Y4.4
OSC1_OUT: R64.1(P1) U14.A4(RTC_XTALOUT)
OSC1_OUT1: C40.2 R64.2(P2) Y4.1
PGOOD_VTT: R184.1 TP22.1 U29.9(PGOOD)
PH: C56.2 D17.1(CATHODE) L3.1 U21.8(PH)
PMIC_I2C_SCL: R69.1(P1) R70.1(P1) U22.9(SCL_SCK)
PMIC_I2C_SDA: R71.1(P1) R72.1(P1) U22.8(SDA_SDI)
PMIC_INTN: TP27.1 U22.45(INT1)
PMIC_PWR_EN: U14.C6(PMIC_POWER_EN) U22.1(PWRHOLD)
PMIC_RESETOUTN: C194.1 R187.2(P2) U14.B15(PWRONRSTN) U22.40(NRESPWRON)
PMIC_SLEEP: TP31.1 U22.37(SLEEP)
PMICSR_I2C_SCL: TP29.1 U22.11(SCLSR_EN1)
PMICSR_I2C_SDA: TP28.1 U22.10(SDASR_EN2)
PR1_MDIO_DATA: R146.2(P2) U14.T13(GPMC_CSN3)
PR1_MDIO_MDCLK: R150.2(P2) U14.V12(GPMC_CLK)
PR1_MII0_RXLINK_SPEED: U4.2(1A) U14.V2(CD_DATA12) U38.9(2Y1)
PR1_MII1_CLK: U2.38(MII_RX_CLK) U14.U16(GPMC_A9)
PR1_MII1_COL_RMII2_CRS_DV: U9.9(3A) U14.T17(GPMC_WAIT0)
PR1_MII1_CRS: U2.40(MII_CRS) U9.10(3B2) U14.R6(LCD_AC_BIAS_EN)
PR1_MII1_RXD0: R135.1(P1) U2.43(MII_RXD_0) U11.10(3B2) U14.V16(GPMC_A8)
PR1_MII1_RXD1: R28.1(P1) U2.44(MII_RXD_1) U9.6(2B2) U14.T15(GPMC_A7)
PR1_MII1_RXD2: R134.1(P1) U2.45(MII_RXD_2) U14.U15(GPMC_A6)
PR1_MII1_RXD3_RMII2_TXD0: U11.12(4A) U14.V15(GPMC_A5)
PR1_MII1_RXDV_RMII2_RXD1: U9.7(2A) U14.T16(GPMC_A10)
PR1_MII1_RXER_RMII2_RXD0: U11.9(3A) U14.V17(GPMC_A11)
PR1_MII1_TXCLK_RMII2_TXEN: U11.4(1A) U14.R13(GPMC_A0)
PR1_MII1_TXD0_RMII2_TXD1: U9.4(1A) U14.R14(GPMC_A4)
PR1_MII1_TXD1: U2.4(MII_TXD_1) U9.3(1B2) U14.T14(GPMC_A3)
PR1_MII1_TXD2: U2.5(MII_TXD_2) U14.U14(GPMC_A2)
PR1_MII1_TXD3: U2.6(MII_TXD_3) U14.V14(GPMC_A1)
PR1_MII1_TXEN_RMII2_RXERR: U11.7(2A) U14.U17(GPMC_WPN)
PR1_MII_CTL: R277.2(P2) R278.2(P2) U14.J17(MII1_RXDV) U37.1(1OE#) U37.19(2OE#) U38.1(1OE#) U38.19(2OE#)
PROFI_GND: J7.1 J9.5
PROFIBUS_A: J8.1 R152.1(P1) U28.12(A)
PROFIBUS_B: J9.8 R153.2(P2) U28.13(B)
PRUETH0_ACTLED: J2.12(D4) R92.1(P1) U3.26(LED_ACT)
PRUETH0_COL: R30.1(P1) U3.42(MII_COL) U8.1(A)
PRUETH0_CRS: U3.40(MII_CRS) U14.H17(MII1_CRS) U14.V5(LCD_PCLK)
PRUETH0_INT: R19.1(P1) U3.7(PWRDNN/INTN)
PRUETH0_JTCK: TP15.1 U3.8(JTAG_TCK)
PRUETH0_JTDI: TP7.1 U3.12(JTAG_TDI)
PRUETH0_JTDO: TP13.1 U3.9(JTAG_TDO)
PRUETH0_JTMS: TP11.1 U3.10(JTAG_TMS)
PRUETH0_JTRSTN: TP9.1 U3.11(JTAG_TRSTN)
PRUETH0_RESETN: U2.29(RESET_N) U3.29(RESET_N) U5.4(Y)
PRUETH0_RXCLK: U3.38(MII_RX_CLK) U14.V4(LCD_DATA14) U38.5(2Y3)
PRUETH0_RXD0: R31.1(P1) U3.43(MII_RXD_0) U14.M16(MII1_RXD0) U14.U4(LCD_DATA11) U38.12(1Y4)
PRUETH0_RXD1: R32.1(P1) U3.44(MII_RXD_1) U14.L15(MII1_RXD1) U14.U3(LCD_DATA10) U38.14(1Y3)
PRUETH0_RXD2: R33.1(P1) U3.45(MII_RXD_2) U14.U2(LCD_DATA9) U38.16(1Y2)
PRUETH0_RXD3: R34.1(P1) U3.46(MII_RXD_3) U14.U1(LCD_DATA8) U38.18(1Y1)
PRUETH0_RXDV: J18.2 TP35.1 U3.39(MII_RX_DV) U14.T5(LCD_DATA15) U38.3(2Y4)
PRUETH0_RXERR: R139.2(P2) U3.41(MII_RX_ERR) U8.2(B) U14.J15(MII1_RXERR)
PRUETH0_RXERR_COL: R139.1(P1) U4.6(2B) U8.4(Y)
PRUETH0_RXERR_COL_PROC: U4.5(2A) U14.V3(LCD_DATA13) U38.7(2Y2)
PRUETH0_SPEEDLED: D4.1(CATHODE) R16.1(P1) TP34.1 U3.27(LED_SPEED) U4.3(1B)
PRUETH0_SWSTRAP: R124.1(P1) U3.21(SW_STRAPN)
PRUETH0_TXCLK: U3.1(MII_TX_CLK) U14.R1(LCD_DATA0) U37.18(1Y1)
PRUETH0_TXD0: U3.3(MII_TXD_0) U14.K17(MII1_TXD0) U14.T2(LCD_DATA5) U37.7(2Y2)
PRUETH0_TXD1: U3.4(MII_TXD_1) U14.K16(MII1_TXD1) U14.T1(LCD_DATA4) U37.9(2Y1)
PRUETH0_TXD2: U3.5(MII_TXD_2) U14.R4(LCD_DATA3) U37.12(1Y4)
PRUETH0_TXD3: U3.6(MII_TXD_3) U14.R3(LCD_DATA2) U37.14(1Y3)
PRUETH0_TXEN: TP32.1 U3.2(MII_TX_EN) U14.J16(MII1_TXEN) U14.R2(LCD_DATA1) U37.16(1Y2)
PRUETH1_ACTLED: J1.12(D4) R97.1(P1) U2.26(LED_ACT)
PRUETH1_COL: R27.1(P1) U2.42(MII_COL) U7.1(A) U9.11(3B1)
PRUETH1_INTN: R18.1(P1) U2.7(PWRDNN/INTN)
PRUETH1_JTCK: TP16.1 U2.8(JTAG_TCK)
PRUETH1_JTDI: TP8.1 U2.12(JTAG_TDI)
PRUETH1_JTDO: TP14.1 U2.9(JTAG_TDO)
PRUETH1_JTMS: TP12.1 U2.10(JTAG_TMS)
PRUETH1_JTRSTN: TP10.1 U2.11(JTAG_TRSTN)
PRUETH1_LINKLED: J1.10(D2) R95.1(P1) TP17.1 U2.28(LED_LINK)
PRUETH1_RXD3: R29.1(P1) U2.46(MII_RXD_3) U11.14(4B1)
PRUETH1_RXDV: J19.2 TP36.1 U2.39(MII_RX_DV) U9.5(2B1)
PRUETH1_RXERR: R138.2(P2) U2.41(MII_RX_ERR) U7.2(B) U11.6(2B2)
PRUETH1_RXERR_COL: R138.1(P1) U7.4(Y) U11.11(3B1)
PRUETH1_SPEEDLED: D5.1(CATHODE) R15.1(P1) TP40.1 U2.27(LED_SPEED) U14.U18(GPMC_BEN1)
PRUETH1_SWSTRAP: R129.1(P1) U2.21(SW_STRAPN)
PRUETH1_TXCLK: U2.1(MII_TX_CLK) U11.2(1B1)
PRUETH1_TXD0: U2.3(MII_TXD_0) U9.2(1B1) U11.13(4B2)
PRUETH1_TXEN: TP33.1 U2.2(MII_TX_EN) U11.3(1B2) U11.5(2B1)
PRUETH_MDC: R148.1(P1) R149.1(P1) R150.1(P1) U2.31(MDC) U3.31(MDC)
PRUETH_MDIO: R145.1(P1) R146.1(P1) R147.1(P1) U2.30(MDIO) U3.30(MDIO)
PRUETHER0_RDN: J2.2 R116.2(P2) U3.13(RD-)
PRUETHER0_RDP: J2.1 R117.2(P2) U3.14(RD+)
PRUETHER0_TDN: J2.6 R118.2(P2) U3.16(TD-)
PRUETHER0_TDP: J2.5 R119.2(P2) U3.17(TD+)
PRUETHER1_RDN: J1.2 R120.2(P2) U2.13(RD-)
PRUETHER1_RDP: J1.1 R121.2(P2) U2.14(RD+)
PRUETHER1_TDN: J1.6 R122.2(P2) U2.16(TD-)
PRUETHER1_TDP: J1.5 R123.2(P2) U2.17(TD+)
PWR_SWIO: L5.1 U22.14(SWIO)
PWR_VAUX1: C53.1 R214.1(P1) U22.46(VAUX1)
PWR_VAUX2: C237.1 R213.1(P1) U22.48(VAUX2)
PWR_VAUX33: C51.1 R78.1(P1) R216.2(P2) U22.4(VAUX33)
PWR_VDAC: C244.1 R77.1(P1) U22.22(VDAC)
PWR_VDD1_SMPS: C67.1 L7.2 R86.2(P2) U22.32(VFB1)
PWR_VDD2_SMPS: C54.1 L4.2 R73.2(P2) U22.44(VFB2)
PWR_VDDIO: R78.2(P2) U22.12(VDDIO)
PWR_VDDS_DDR: C65.1 L5.2 R85.2(P2) U22.16(VFBIO)
PWR_VDIG1: C49.1 R218.2(P2) U22.7(VDIG1)
PWR_VDIG2: C50.1 R217.2(P2) U22.5(VDIG2)
PWR_VMMC: C52.1 R215.2(P2) U22.2(VMMC)
PWR_VPLL: C245.1 R76.1(P1) U22.24(VPLL)
PWRON: TP30.1 U22.33(PWRON)
RESN: J17.6 R230.2(P2)
RTC_PORZ: R176.2(P2) U13.7(2Y) U14.B5(RTC_PWRONRSTN)
RTCK: J15.9(TCKRTN) R22.1(P1)
SENSE: R66.2 R67.1(P1) U21.4(VSNS)
SPI0_CS0: U14.A16(SPI0_CS0) U17.1(C\S\)
SPI0_CS1: U14.C15(SPI0_CS1) U35.24(C\E\)
SPI0_D0: R75.1(P1) TP39.1 U14.B17(SPI0_D0) U17.2(DO) U20.4(Y)
SPI0_D1: TP38.1 U14.B16(SPI0_D1) U17.5(DI)
SPI0_SCLK: U14.A17(SPI0_SCLK) U17.6(CLK) U35.25(CLK)
SPI1_CS0: J3.18 U14.C12(MCASP0_AHCLKR)
SPI1_D0: J3.14 U14.B13(MCASP0_FSX)
SPI1_D1: J3.16 U14.D12(MCASP0_AXR0)
SPI1_SCLK: J3.12 U14.A13(MCASP0_ACLKX)
SW3: U22.31(SW3)
SYS_BOOT0: R57.1(P1) R157.2(P2) U37.2(1A1)
SYS_BOOT1: J5.2 U37.4(1A2)
SYS_BOOT2: R56.1(P1) R158.2(P2) U37.6(1A3)
SYS_BOOT3: R55.1 R159.2(P2) U37.8(1A4)
SYS_BOOT4: R54.1 R160.2(P2) U37.11(2A1)
SYS_BOOT5: R53.1(P1) R161.2(P2) U37.13(2A2)
SYS_BOOT6: R52.1(P1) R162.2(P2) U37.15(2A3)
SYS_BOOT7: R51.1(P1) R163.2(P2) U37.17(2A4)
SYS_BOOT8: R50.1 R164.2(P2) U38.2(1A1)
SYS_BOOT9: R49.1(P1) R165.2(P2) U38.4(1A2)
SYS_BOOT10: R47.1(P1) R167.2(P2) U38.6(1A3)
SYS_BOOT11: R45.1 R169.2(P2) U38.8(1A4)
SYS_BOOT12: R48.1(P1) R166.2(P2) U38.11(2A1)
SYS_BOOT13: R46.1(P1) R168.2(P2) U38.13(2A2)
SYS_BOOT14: R44.1 R170.2(P2) U38.15(2A3)
SYS_BOOT15: R43.1(P1) R171.2(P2) U38.17(2A4)
SYS_RESETN: R20.2(P2) R105.1(P1) R142.1(P1) R197.1(P1) R198.2(P2) R230.1(P1) U5.2(B) U14.A10(WARMRSTN)
SYS_WARMRESETN: C235.1 R198.1(P1) S1.2(A2)
TCK: J15.11(TCK) R23.1(P1)
TDIS: J15.4(TDIS) R17.2(P2)
TEMP_SENSE: U14.B6(AIN0) U19.3(OUT)
TESTOUT: TP24.1(TP) U14.A3(RESERVED)
UART0_RXD: R181.1 U14.E15(UART0_RXD)
UART0_TXD: C184.1 R186.1 U14.E16(UART0_TXD)
UART1_RXD: U14.D16(UART1_RXD) U28.5(R)
UART1_TXD: U14.D15(UART1_TXD) U28.8(D)
UART3_RXD: U14.L17(MII1_RXD3) U18.38(BDBUS0)
UART3_TXD: U14.L16(MII1_RXD2) U18.39(BDBUS1)
UART4_RXD_SYNC0_OUT: J3.7 U14.E18(UART0_CTSN)
UART4_TXD_SYNC1_OUT: J3.8 U14.E17(UART0_RTSN)
USB_DC: C263.1 C264.1 J13.1(VBUS) R189.2 U23.6(VBUS)
USBDM: J13.2(DM) L6.3 U23.2(D-)
USBDM_FT: L6.2 U18.7(DM)
USBDP: J13.3(DP) L6.4 U23.1(D+)
USBDP_FT: L6.1 U18.8(DP)
VADD33_PRUETH0: C2.1 C5.1 R8.1(P1) R241.1(P1) U3.22(AVDD33)
VADD33_PRUETH1: C1.1 C3.1 R7.1(P1) R240.1(P1) U2.22(AVDD33)
VAUX1: C21.1 C124.1 C132.1 R39.2(P2) R214.2(P2) U12.3(VDD) U14.N16(VDDA1P8V_USB0) U14.R16(VDDA1P8V_USB1)
VAUX2: C23.1 C29.1 C47.1 C109.2 C110.2 C111.2 C112.1 C113.1 C137.2 C139.1 C143.2 C172.2 C173.2 C175.2 C189.1 C193.1 C201.1 C202.2 C205.1 R37.2 R43.2(P2) R44.2 R45.2 R46.2(P2) R47.2(P2) R48.2(P2) R49.2(P2) R50.2 R51.2(P2) R52.2(P2) R53.2(P2) R54.2 R55.2 R56.2(P2) R57.2(P2) R61.2(P2) R70.2(P2) R71.2(P2) R196.2(P2) R197.2(P2) R213.2(P2) U14.E10(VDDSHV6#E10) U14.E11(VDDSHV6#E11) U14.E12(VDDSHV6#E12) U14.E13(VDDSHV6#E13) U14.F14(VDDSHV6#F14) U14.G14(VDDSHV6#G14) U14.K14(VDDSHV5#K14) U14.L14(VDDSHV5#L14) U14.N5(VDDSHV6#N5) U14.P5(VDDSHV6#P5) U14.P6(VDDSHV6#P6) U14.P7(VDDSHV1#P7) U14.P8(VDDSHV1#P8) U14.P12(VDDSHV3#P12) U14.P13(VDDSHV3#P13) U32.1(EN)
VAUX33: C116.1 C120.1 C186.1 R63.2 R184.2 R208.2(P2) R216.1(P1) U14.N15(VDDA3P3V_USB0) U14.R15(VDDA3P3V_USB1) U29.10(VIN)
VBREF: C267.1 J17.9
VCAN: J6.1 J9.9
VCAN0: C24.1(POS) C98.1 C107.1 C185.1 C191.1(POS) J6.2 J10.2 R152.2(P2) U16.8(VCC2) U27.7(OUT#7) U27.8(OUT#8) U28.16(VCC2)
VCOMH: C63.1 J17.2
VDAC: C114.1 C152.1 C177.1 C182.1 C212.1 R77.2(P2) U14.E6(VDDS#E6) U14.E14(VDDS#E14) U14.F9(VDDS#F9) U14.K13(VDDS#K13) U14.N6(VDDS#N6) U14.P9(VDDS#P9) U14.P14(VDDS#P14)
VDIG1: R218.1(P1) TP26.1
VDIG2: C106.1 C108.1 C135.1 C166.1 C181.1 C196.1 R217.1(P1) U14.D10(VDDS_SRAM_MPU_BB) U14.E7(VDDS_PLL_DDR) U14.E9(VDDS_SRAM_CORE_BG) U14.H15(VDDS_PLL_MPU) U14.R10(VDDS_PLL_CORE_LCD) U14.R11(VDDS_OSC)
VMMC: C68.1 C119.2 C121.2 C157.2 C160.2 C179.2 C229.2 C260.1 C272.1 J16.4(VDD) R215.1(P1) R231.2(P2) R233.2(P2) R234.2(P2) R235.2(P2) R236.2(P2) R237.2(P2) U14.H14(VDDSHV4#H14) U14.J14(VDDSHV4#J14) U14.P10(VDDSHV2#P10) U14.P11(VDDSHV2#P11) U24.10(VCC)
VPLL: FB2.2 R76.2(P2)
VPMIC_VRTC: C261.1 R228.2(P2) U22.29(VRTC)
VPP: U14.M5(VPP)
VPROFI_DB: J9.6 J10.1
VPROFI_SRC: C95.1 C96.1 D11.1(CATHODE) D13.1(CATHODE) U27.5(IN#5) U27.6(IN#6)
VPROFI_TRANSA: D13.2(ANODE) L1.8
VPROFI_TRANSB: D11.2(ANODE) L1.5
VREFP_ADC: C33.1 C34.1 C35.1 R60.1(P1) U14.B9(VREFP)
VRTC: C125.1 C197.1 C223.1 U13.5(2A) U13.6(2B) U13.8(VCC) U14.D7(VDDS_RTC) U30.5(OUT)
VRTC_DET: R177.1(P1) U13.3(2Y)
VRTC_DETB: C148.1 R177.2(P2) U13.1(2A) U13.2(2B)
VTT_DDR: C32.1 C38.1 C39.1 C41.1 C214.1 C215.1 R180.2 RP1.9 RP1.10 RP1.11 RP1.12 RP1.13 RP1.14 RP1.15 RP1.16 RP2.11 RP2.12 RP2.13 RP2.14 RP2.15 RP2.16 RP3.9 RP3.10 RP3.11 RP3.12 RP3.13 RP3.14 RP3.15 RP3.16 U29.3(VO) U29.5(VOSNS)
XTIN: C211.2 U18.2(XTIN) Y2.3(X3)
XTOUT: C222.2 U18.3(XTOUT) Y2.1(X1)
N16792759: R174.2(P2) U28.6(R\E\)
N16818242: C6.1 C16.1 C81.1 C82.1 U3.18(PFBIN1) U3.23(PFBOUT) U3.37(PFBIN2)
N16818333: R8.2(P2) U3.20(RSV)
N16818596: J2.9(D1) R89.1(P1)
N16819128: R10.2(P2) U3.24(RBIAS)
N16839102: C262.1 R227.1(P1) U35.14(VCC)
N16839202: R82.2(P2) U35.13(RLIM)
N16839209: R223.2(P2) U35.2(DB1)
N16839216: R222.2(P2) U35.1(DB0)
N16844016: D15.2(ANODE) R173.2(P2)
N16844076: D14.2(ANODE) R155.2(P2)
N16844150: D12.2(ANODE) R151.2(P2)
N16844168: D10.2(ANODE) R143.2(P2)
N16844256: D9.2(ANODE) R140.2(P2)
N16844274: D8.2(ANODE) R136.2(P2)
N16844366: D7.2(ANODE) R133.2(P2)
N16844384: D6.2(ANODE) R132.2(P2)
N17075237: D4.2(ANODE) R130.1(P1)
N17107785: C254.1 U22.18(VREF)
N17123334: L7.1 U22.35(SW1)
N17123833: L4.1 U22.42(SW2)
N19577113: R229.1(P1) U22.26(BOOT0)
N19577116: R228.1(P1) U22.19(BOOT1)
N20350418: J5.3 R38.2(P2)
N20364263: TP23.1 U14.C5(EXT_WAKEUP)
N21063525: R101.1(P1) U1.F6(B\Y\T\E\)
N21210919: R224.2(P2) R225.1(P1) U34.4(EN)
N21210937: D20.2(ANODE) L2.2 U34.1(SW)
N21211001: C255.2 R220.1(P1) R221.2(P2) U34.3(FB)
N21251713: J2.11(D3) R93.1(P1)
N21451174: R199.1(P1) U17.3(W\P\)
N21451189: R200.1(P1) U17.7(H\O\L\D\)
N21620210: C259.1 R226.2(P2) U35.3(IP0)
N21620213: C256.1 R84.2(P2) U35.5(IP1)
N21620216: C253.1 R83.2(P2) U35.7(IP2)
N21620219: C250.1 R81.2(P2) U35.9(IP3)
N21620222: C247.1 R80.2(P2) U35.11(IP4)
N21620225: C246.1 R79.2(P2) U35.18(IP5)
N21620228: C241.1 R74.2(P2) U35.20(IP6)
N21620231: C239.1 R68.2(P2) U35.22(IP7)
N21797281: R40.2(P2) U9.15(OE#)
N21797333: R41.2(P2) U11.15(OE#)
N21800158: C162.1 R179.2 R182.2
N21868977: C216.1 R191.1 R195.2 U29.1(REFIN)
N21870936: R183.2 U15.L8(ZQ)
N21881059: D5.2(ANODE) R131.1(P1)
N21881073: J1.11(D3) R98.1(P1)
N21881115: J1.9(D1) R94.1(P1)
N21881265: C4.1 C14.1 C83.1 C84.1 U2.18(PFBIN1) U2.23(PFBOUT) U2.37(PFBIN2)
N21881353: R7.2(P2) U2.20(RSV)
N21881950: R9.2(P2) U2.24(RBIAS)
N22333314: R88.2(P2) SW1.1(P0) U25.1(P0)
N22333318: R99.2(P2) SW1.2(P1) U25.2(P1)
N22371955: C43.1 U32.5(FB)
N23086594: R13.1 U3.25(CLKOUT)
N23086888: R12.1 U2.25(CLKOUT)
N27955689: R188.2 R189.1 U18.59(BCBUS7)
N27956453: R142.2(P2) U10.4(Y)
N28554546: D1.2(R) R1.2(P2)
N28554548: D1.4(Y) R2.2(P2)
N28554589: Q2.3 R1.1(P1)
N28554595: Q1.6(3) R3.1(P1)
N28554605: Q1.3 R2.1(P1)
N28554613: D1.3(G) R3.2(P2)
N28559145: D2.2(R) R4.2(P2)
N28559147: D2.4(Y) R5.2(P2)
N28559250: D2.3(G) R6.2(P2)
N28559254: Q3.6(3) R4.1(P1)
N28559256: Q2.6(3) R5.1(P1)
N28559275: Q3.3 R6.1(P1)
N28559577: D3.1(CATHODE) Q4.6(3)
N28559579: D3.2(ANODE) R128.1(P1)
N28559581: Q4.2(5) R126.1(P1) R127.2(P2)
N28614111: D18.1(CATHODE) F1.1
N28629254: D16.2(ANODE) R208.1(P1)
N28737675: R58.2(P2) U14.G17(MMC0_CLK)
N28753994: R100.2(P2) SW1.4(P2) U25.3(P2)
N28754074: R87.2(P2) SW1.8(P3) U25.5(P3)
N28785526: J19.1 R112.2(P2)
N28785533: J19.3 R110.2(P2)
N28944514: J18.1 R114.2(P2)
N28944521: J18.3 R113.2(P2)
N29141166: C89.2 U12.14(XOUT) Y1.1
N29141233: C90.2 U12.1(XIN/CLK) Y1.2
N29141536: R39.1(P1) U12.2(S0)
N29149555: R42.1 U12.8(Y3)
N29149585: R154.1 U12.9(Y2)
N29149616: R144.1 U12.11(Y1)
N29208060: J5.1 R37.1

Pads without a net: J1 7; J2 7; J9 1 4; J13 4; J15 6; J16 10; NOREF#11 1; NOREF#14 1; NOREF#17 1; NOREF#18 1; NOREF#19 1; Q4 3 4 5; R212 3 4; R219 3 4; RP2 7 8 9 10; U1 B3 C4 D3; U2 33; U3 33; U6 7; U9 12; U10 1; U12 4; U14 B18 D3 M15 N17 N18 P15 P16 P17 P18 R17 R18 T18; U15 J1 J9 L1 L9 M7; U18 22 24 27 29 33 34 36 40 41 43 44 45 46 48 52 53 54 55 57 58 60; U20 1; U21 2 3 5; U22 21 25 38 39; U23 3 5; U24 4 9; U27 1 2; U28 10; U30 4; U35 4 6 8 10 12 16 17 19 21 27; Y2 2 4; Y3 2 4; Y4 2 3

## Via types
v1: diameter 0.457, hole 0.203, TOP to BOTTOM, 1028 vias
v2: diameter 0.559, hole 0.305, TOP to BOTTOM, 506 vias

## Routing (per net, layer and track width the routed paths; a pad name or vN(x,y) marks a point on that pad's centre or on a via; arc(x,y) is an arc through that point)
AGND_CAN: length 31
  BOTTOM w0.584: R175.1 5.71,52.7 3.38,52.7 J9.11
  BOTTOM w0.762: J9.11 4.84,51.12 4.84,41.76 4.76,41.69 4.76,37.02 4.84,36.94 4.84,30.16 J9.10
AGND_PRUETH0: length 15.9
  TOP w0.203: U3.15 v1(56.87,81.4) ; U3.19 v1(54.87,81.41)
  TOP w0.381: C5.2 C2.2 49.91,84.33 v2(49.91,84.33)
  LYR4 w0.508: v1(56.87,81.4) 56.49,81.03 55.25,81.03 v1(54.87,81.41) 54.86,81.41 54.22,80.76 51.15,80.76 50.42,81.49 50.42,83.82 50.04,84.2 50.04,84.2 v2(49.91,84.33)
  BOTTOM w0.508: R242.1 50.79,85.21 v2(49.91,84.33)
AGND_PRUETH1: length 14.8
  TOP w0.305: U2.15 v1(40.49,81.41) ; v1(38.49,81.41) U2.19
  TOP w0.381: R239.1 33.03,84.98 v2(33.08,85.03) ; v2(34.54,85.09) C1.2 C3.2
  LYR4 w0.508: v2(33.08,85.03) 34.48,85.03 v2(34.54,85.09) 34.54,84.07 35.81,82.8 37.09,82.8 v1(38.49,81.41) 38.49,81.4 38.99,81.4 39,81.41 v1(40.49,81.41)
AGNDFRAME_PRUETH0: length 24.5
  LYR4 w0.635: 55.55,94.87 56.24,94.18 66.61,94.18 J2.13 ; 55.55,94.87 54.86,94.18 50.86,94.18 J2.14 ; 55.55,94.87 55.55,97.54 55.52,97.67 55.52,98.07 57.85,100.39 v2(58.74,100.39)
  BOTTOM w0.381: R91.1 v2(58.74,100.39)
AGNDFRAME_PRUETH1: length 24.5
  LYR4 w0.635: v2(38.42,100.39) 37.53,100.39 35.2,98.07 35.2,97.67 35.23,97.54 35.23,94.87 ; J1.14 30.54,94.18 34.54,94.18 35.23,94.87 ; 35.23,94.87 35.92,94.18 46.29,94.18 J1.13
  BOTTOM w0.508: R96.1 v2(38.42,100.39)
DGND: length 652.5
  TOP w0.203: v2(16.35,10.39) 16.22,10.25 U22.17 ; v1(12.83,32.26) 12.83,32.46 12.58,32.71 U18.1 ; U22.34 19.05,8 v2(19.4,8.35) ; U22.30 17.45,8.27 v2(17.37,8.35) ; v2(16.35,9.37) 16.04,9.05 U22.20 ; v2(19.4,10.39) 19.94,9.85 U22.43 ; U22.15 16.01,11.05 v2(16.35,11.4) ; U13.4 25.13,44.14 v1(24.87,43.87) ; 39,53.46 39,54.56
  TOP w0.254: v1(57.4,38.54) 58.81,38.54 U15.T1 ; v1(57.8,41.61) 58.87,41.61 U15.M1 ; v1(60.07,47.62) 60.07,47.62 U15.E2 ; U15.G8 v1(64.9,45.25) ; v1(25.16,83.85) 25.09,83.92 25.09,83.92 U1.H1 ; C19.2 v1(34.8,64.01) ; U9.14 31.48,63.36 v1(31.24,63.12) 30.98,63.38 U9.13 ; U15.F9 v1(65.87,46.45) ; v1(58.35,45.74) 58.81,45.74 U15.G1 ; U9.8 28.56,66.54 28.15,66.95 28.15,67.19 v1(28.14,67.2) ; v1(39.12,63.62) U11.8 ; v2(22.91,33.48) 22.05,33.48 21.54,32.96 21.54,32.45 21.78,32.21 U18.47 ; v1(54.02,34.04) C31.2 C30.2 53.59,34.75 53.59,34.88 v1(54.02,35.31) ; U15.J8 64.84,43.71 64.87,43.71 v1(64.9,43.68) ; U15.A9 v1(65.87,50.45) ; U15.D1 58.79,48.16 v1(58.01,48.16) ; U15.J2 v1(60.1,44.45) ; U15.B1 58.37,50.19 v1(58.37,50.4) ; v1(57.51,46.73) 58.03,47.25 U15.E1 ; v1(66.04,41.91) 65.78,41.65 U15.M9 ; U15.B9 v1(65.87,49.65) ; U15.T9 v1(65.87,38.45) ; U15.P1 v1(57.71,40.05) ; U15.E8 v1(64.1,46.85) ; U15.D8 v1(64.9,47.65) ; U1.H6 v1(25.17,88.63) ; U15.B3 v1(61.14,49.65) ; U15.G9 v1(65.87,45.65) ; U15.P9 v1(64.9,39.65)
  TOP w0.305: v1(40.17,45.25) U14.K9 ; U14.J6 v1(42.57,43.65) U14.H6 ; U14.M7 v1(41.77,46.05) U14.M6 ; U14.M9 v1(40.17,46.85) U14.M8 ; U14.L11 v1(37.77,46.05) U14.M12 ; v1(57.91,70.48) 57.37,71.03 U3.47 ; U14.L12 v1(36.97,46.05) U14.L13 ; U18.11 10.39,27.71 v1(10.16,27.94) 10.43,28.21 U18.10 ; U2.47 40.98,70.75 v1(40.98,70.74) ; U14.A18 32.38,37.46 32.38,37.18 v1(32.34,37.14) ; U14.K7 U14.J7 v1(41.77,43.65) ; v2(31.8,76.01) 31.62,75.84 C9.2 ; U14.L10 v1(38.57,45.25) U14.K10 ; U18.32 20.77,24.27 20.52,24.52 v1(20.52,24.63) ; U14.N14 v1(35.37,46.85) U14.M14 ; U14.H10 v1(38.57,43.65) U14.J10 ; v1(41.77,47.65) U14.N7 ; U14.G11 v1(37.77,42.85) U14.G12 ; U18.15 v1(12.83,25.71) 12.83,26.28 12.4,26.71 U18.13 ; v1(40.97,42.85) U14.H8 ; C11.2 v1(59.31,68.96) ; v1(36.97,42.85) U14.H12 v1(37.77,43.65) U14.J11 ; U14.G9 v1(40.17,42.05) U14.F8 ; v1(37.77,45.25) U14.K11 ; U14.G8 v1(40.17,42.85) U14.H9 ; U14.N11 v1(38.57,47.65) U14.N10 ; U18.5 12.6,30.71 v1(12.83,30.48) ; U14.V1 v1(46.17,51.94) ; U14.V18 v1(32.13,51.69) ; U18.51 19.77,35.53 19.51,35.79 v1(19.05,35.79) ; v1(33.38,73.41) 33.4,73.43 33.4,73.66 33.56,73.82 U2.35 ; U2.36 34.08,73.32 33.59,72.83 v1(33.47,72.83) ; C15.2 v1(42.29,68.33) ; U14.H7 v1(41.77,42.85) ; v1(38.57,46.85) U14.M10 ; v1(46.12,37.14) 46.17,37.14 U14.A1 ; v1(40.17,43.65) U14.J9 ; U18.25 v1(17.27,24.63) ; v1(40.97,43.65) U14.J8
  TOP w0.381: v2(63.13,29.97) 63.61,29.97 63.68,29.91 63.82,29.91 C41.2 ; R41.1 42.98,58.8 42.6,58.42 v2(42.42,58.42) ; R10.1 50.93,81.92 v2(51.31,81.53) ; v1(76.49,65.12) 76.26,65.12 76.24,65.11 74.95,65.11 74.46,65.6 C13.2 ; C52.2 v1(21.59,21.34) ; v2(38.23,85.34) 39.62,83.95 C4.2 ; U37.10 v2(59.95,58.04) ; C38.2 64.74,33.26 v1(64.47,32.99) ; R9.1 v1(33.78,82.17) ; v2(63.25,72.26) 63.48,72.02 U10.3 ; v2(31.18,85.02) 31.23,84.97 R239.2 ; C7.2 v2(70.61,75.82) ; U16.4 14.61,45.09 v2(14.22,45.47) ; R40.1 33.62,62.23 33.62,62.15 33.55,62.15 33.55,62.14 v2(33.61,62.14) ; R17.1 C8.2 75.99,72.09 76.25,72.34 v1(76.63,72.34) ; U20.3 50.66,23.32 v2(51.01,23.67) ; C14.2 v1(35.18,68.33) ; v1(2.03,22.35) 2.54,22.86 S1.1 ; v2(71.53,70.82) 70.86,70.14 U4.4 ; v1(39.78,30.72) 39.48,30.72 U19.5 ; U12.10 73.26,56.88 v2(72.9,56.52) ; v2(54.53,85.47) 56.01,84 C6.2 ; U23.4 v2(2.5,6.29) ; U3.35 U3.36 50.92,73.03 v2(51.31,72.64) v2(50.29,72.64) ; C21.2 65.86,57.78 v2(65.51,58.14) ; v2(51.95,63.73) 51.94,63.73 R278.1 ; R62.1 67.95,33.69 67.55,34.1 v2(67.5,34.1) ; C65.2 10.77,5.35 v2(10.37,5.75) ; C277.2 v2(53.09,63.75) ; v2(37.92,25.74) 39.27,24.39 C48.2 ; 2.41,70.48 2.41,69.01 v1(2.45,68.97) ; 54.63,32.26 C39.2 ; 54.63,32.26 54.63,31.99 v2(55.5,31.11) ; 54.63,32.26 54.63,33.26 54.52,33.36 54.52,33.42 v2(54.5,33.42) ; v1(4.99,68.9) 4.95,68.94 4.95,70.48 ; D16.1 27.69,22.1 v2(27.3,21.72) ; R66.1 43.17,24.64 v1(42.82,24.99) ; C10.2 v2(47.24,75.31) ; C49.2 v1(15.49,21.34) ; v2(52.4,51.05) 52.32,51.05 51.32,52.05 C27.2 ; v2(23.83,24.18) 23.83,24.88 24.07,25.13 C47.2 ; v2(52.65,24.38) 52.58,24.38 52.45,24.51 51.86,24.51 C45.2 51.78,25.27 52.29,25.27 v2(52.56,25.54) ; C32.2 55.5,33.66 55.37,33.78 v2(55.37,34.42) ; v2(47.5,73.41) 47.74,73.17 U5.3 ; 3.68,70.48 v1(3.68,69.12) ; v2(63.14,63.64) C23.2 v2(65.64,63.64) ; C51.2 v1(19.56,21.34) ; v2(7.53,5.52) 7.49,5.52 7.65,5.36 J13.5 ; 6.22,70.48 v1(6.22,71.84) ; C17.2 v2(49.66,67.82) ; U12.5 69.74,56.88 v2(69.98,56.64) ; v1(31.88,32.49) 31.88,32.13 32.26,31.75 U17.4 32.64,31.81 32.64,32.89 ; C16.2 v2(50.55,68.33) ; C29.2 26.04,35.04 v2(26.04,33.53) ; U18.35 21.42,26.21 v1(21.24,26.38) ; v2(52.22,35.69) 51.55,35.69 C28.2 ; U19.2 40.13,28.62 v1(40.01,28.74) ; R65.2 v2(46.99,32.38) ; R14.1 v2(75.47,75.52) ; C68.2 15.62,3.13 v2(15.45,3.3) 14.22,3.3 13.88,2.96 C66.2 ; v1(17.17,21.34) 17.53,20.98 C50.2 ; v2(45.09,65.28) 45.09,65.79 44.85,66.03 U7.3 ; C53.2 v1(23.62,21.34) ; U24.5 v2(17.83,4.45) ; 40.51,66.8 v2(40.51,67.56) ; R38.1 v2(66.17,62.23) ; U8.3 v2(36.01,64.9)
  TOP w0.508: C22.2 65.83,55.5 65.7,55.63 65.28,55.63 v2(64.9,56.01) ; v2(63.63,12.45) 64.37,12.45 C60.2 v2(63.5,13.22) ; 45.21,61.09 v2(45.97,61.09) ; R82.1 51.44,13.97 51.82,14.35 v2(52.45,14.35) ; v2(19.56,17.65) C58.2 ; C63.2 C62.2 64.19,10.4 63.54,11.05 v2(62.74,11.05) ; C57.2 v2(17.53,17.55) ; v1(53.47,18.51) 53.46,18.51 53.17,18.22 53.15,18.22 52.96,18.03 C55.2 ; C12.2 v1(47.24,69.22) ; U21.6 v1(41.91,20.95) ; C59.2 v2(21.21,17.55)
  TOP w0.635: C67.2 v2(32.5,2.05) ; C64.2 v2(28.32,7.87) ; C54.2 v2(25.91,21.34) ; C61.2 v2(28.32,9.65)
  LYR2_GND w0.889: 4.26,92 J3.15 ; J3.15 4.26,90.5 ; J3.15 5.77,92 ; J3.15 5.77,90.5 ; MH3.1 5.49,17.55 ; MH3.1 5.49,14.2 ; MH3.1 2.13,14.2 ; MH3.1 2.13,17.55 ; 33.22,89.09 J1.8 ; J1.8 34.72,89.09 ; J1.8 33.22,87.59 ; J1.8 34.72,87.59 ; J14.30 74.03,39.23 ; J14.30 74.03,37.73 ; J14.30 72.53,39.23 ; J14.30 72.53,37.73 ; TP18.1 22.03,62.25 ; TP18.1 20.34,63.94 ; TP18.1 22.03,63.94 ; TP18.1 20.34,62.25 ; 75.07,22.49 J14.17 ; J14.17 76.57,22.49 ; J14.17 76.57,23.99 ; J14.17 75.07,23.99 ; TP19.1 46.69,70.82 ; TP19.1 45.01,69.14 ; TP19.1 46.69,69.14 ; TP19.1 45.01,70.82 ; J2.8 55.04,87.59 ; J2.8 53.54,87.59 ; J2.8 55.04,89.09 ; J2.8 53.54,89.09 ; 3.09,101.05 MH1.1 ; MH1.1 6.44,97.7 ; MH1.1 6.44,101.05 ; MH1.1 3.09,97.7 ; J14.29 76.57,37.73 ; J14.29 76.57,39.23 ; J14.29 75.07,37.73 ; J14.29 75.07,39.23 ; J14.18 74.03,23.99 ; J14.18 74.03,22.49 ; J14.18 72.53,23.99 ; 39.99,8.04 J11.2 ; J11.2 39.99,5.01 ; J11.2 43.02,8.04 ; J11.2 43.02,5.01 ; 35.19,4.79 J11.3 ; J11.3 35.19,1.76 ; J11.3 38.22,4.79 ; J11.3 38.22,1.76 ; 1.72,74.22 J3.2 ; J3.2 3.23,72.72 ; J3.2 1.72,72.72 ; J3.2 3.23,74.22 ; MH2.1 75.4,97.7 ; MH2.1 75.4,101.05 ; MH2.1 72.05,97.7 ; MH2.1 72.05,101.05 ; 65,5.49 MH4.1 ; MH4.1 65,2.13 ; MH4.1 68.35,2.13 ; MH4.1 68.35,5.49
  BOTTOM w0.254: Q4.1 73.37,86.09 v2(72.85,85.57) ; C115.2 57.74,50.57 57.91,50.4 v1(58.37,50.4) ; v1(21.12,73.51) 21.11,73.51 21.11,73.64 20.97,73.77 U26.15 ; C183.2 57.31,38.45 v1(57.4,38.54) ; Q1.4 v2(74.95,96.52) ; v1(26.77,76.17) U26.28 ; C172.1 39.32,38.71 38.99,39.04 38.99,39.23 v1(38.57,39.65) ; v1(58.01,48.16) 57.99,48.18 57.5,48.18 C126.2 ; C144.2 66.01,45.51 v1(65.87,45.65) ; Q3.4 73.45,88.8 v2(73.18,88.53) ; Q1.1 73.43,94.5 v2(71.32,94.5) ; v2(75.85,93.1) 75.58,93.37 Q2.4 ; v1(57.8,41.61) 57.42,41.61 C174.2 ; v1(65.87,46.45) 65.98,46.56 C136.2 ; U29.8 v2(68.33,34.54) ; v1(21.21,71.77) U26.10 ; C140.2 58.28,45.67 v1(58.35,45.74) ; v1(65.87,50.45) 65.46,50.04 C117.2 ; v1(17.11,76.48) 17.77,76.48 18.08,76.17 U26.21 ; U26.4 v1(21.21,69.37) ; v1(65.87,49.65) 65.94,49.58 C122.2 ; Q2.1 72.56,92.07 v2(72.17,92.47) ; C118.2 61.01,49.78 v1(61.14,49.65) ; v1(27.39,71.99) 27.17,71.77 U26.39 ; C146.2 59.99,44.56 v1(60.1,44.45) ; v2(75.85,91.83) 75.85,91.2 75.61,90.96 Q3.1 ; U26.1 v1(21.21,68.17) ; v2(67.5,34.1) 67.83,33.77 U29.4 ; U26.24 18.97,77.37 18.11,78.23 16.62,78.23 16.6,78.21 v1(16.64,78.21) ; J17.8 v2(57.56,2.7) ; v1(60.07,47.62) 59.99,47.71 C128.2 ; v1(64.9,47.65) 64.72,47.83 C127.2 ; v1(26.73,73.77) U26.34 ; U26.45 v1(24.2,69.37)
  BOTTOM w0.305: C169.2 v1(40.97,42.85) ; v1(40.17,46.85) 39.88,47.14 C130.2 ; C149.2 41.48,43.94 v1(41.77,43.65) ; C173.1 36.17,41.14 v1(36.17,40.45) ; C135.2 v1(37.77,46.05) ; U35.28 v2(60.49,18.29) ; C134.2 41.08,47.65 v1(41.77,47.65) ; v1(40.17,42.05) 39.88,41.76 C181.2 ; C160.1 v1(36.97,42.85)
  BOTTOM w0.381: C233.2 48.57,24.51 51.18,24.51 v2(51.82,23.88) ; v2(49.78,4.06) 49.66,4.19 C262.2 ; C203.2 C202.1 C201.2 C200.2 C199.2 C198.2 C197.2 C196.2 43.31,33.15 v1(43.56,32.89) ; C203.2 C204.2 35.18,33.91 v1(35.05,33.78) 34.81,33.54 34.66,33.54 34.15,33.04 C210.2 32.85,33.04 32.77,32.96 32.34,32.96 v1(31.88,32.49) ; C203.2 36.2,34.04 36.43,33.8 36.43,33.78 v1(36.74,33.48) ; C120.2 31.16,49.45 v1(30.48,49.45) ; C120.2 C124.2 C132.2 C137.1 30.61,46.48 v1(30.48,46.35) ; C120.2 C116.2 ; C69.2 v2(21.72,100.53) ; v2(71.25,12.19) 70.36,11.3 C253.2 ; C241.2 C246.2 ; C246.2 70.36,16.64 v2(71.25,17.53) ; C246.2 C247.2 ; R171.1 v2(53.34,66.93) ; R171.1 R170.1 R166.1 ; R171.1 R168.1 R169.1 ; C71.2 v1(61.79,95.38) ; C240.2 51.05,17.53 v2(51.44,17.14) ; R100.1 v2(28.19,96.9) ; v2(67.32,30.27) 67.11,30.48 66.18,30.48 C217.2 65.68,29.97 v2(64.87,29.97) ; C231.2 v1(14.48,22.1) ; C75.2 v1(26.16,86.23) ; v2(56.01,78.99) 55.5,79.5 C82.2 ; C187.2 32.28,37.95 32.28,37.26 32.34,37.19 v1(32.34,37.14) 32.34,37.11 32.26,37.02 C192.2 ; R157.1 R159.1 ; R159.1 v2(61.47,66.93) ; R159.1 R158.1 R160.1 ; C268.2 v2(57.15,8) ; U31.7 v1(53.47,20.95) ; v2(42.16,86.11) 42.04,85.98 42.04,85.34 ; U31.16 v1(61.09,25.53) ; R169.1 R167.1 R165.1 ; R169.1 v2(51.31,66.93) ; v2(7.26,62.43) 6.6,62.43 6.22,62.81 C93.2 ; v1(20.95,35.81) 21.59,35.81 22.1,35.31 C206.1 ; C275.2 44.78,55.63 v2(44.53,55.37) 44.53,55.3 45.47,54.36 R277.1 ; v2(60.07,55.41) 59.23,55.41 C101.2 59.17,54.61 v2(59.97,54.61) ; v2(60.07,29.06) 60.58,29.06 60.73,29.21 61.71,29.21 C215.2 62.91,29.23 v2(63.36,28.78) ; v2(35.32,25.72) 35.32,25.41 34.81,24.91 33.22,24.91 32.89,24.58 U30.2 ; v1(10.16,27.94) 10.33,27.94 10.58,27.69 C224.2 ; R127.1 70.54,85.85 70.52,85.87 v2(70.44,85.87) ; C159.2 v1(48.13,42.55) ; v2(75.85,93.1) 76.23,93.48 R107.1 ; v1(67.51,65.41) 67.51,65.49 67.77,65.74 J15.16 ; v2(52.32,78.87) 51.96,79.23 C81.2 ; v1(38.35,26.92) 38.35,27.5 FB11.2 ; v2(63.13,29.97) 63.25,30.1 C214.2 ; 29.84,41.78 30,41.78 30.4,42.18 31.23,42.18 C166.2 C157.1 30.86,43.18 30.61,42.93 v1(30.51,42.93) ; C232.1 v1(2.03,22.35) ; v2(52.4,51.05) 52.21,51.24 52.13,51.24 51.55,51.83 C104.2 v2(51.55,53.38) ; C78.2 v2(54.53,85.47) ; C131.2 35.37,47.54 v1(35.37,46.85) ; R102.1 v2(25.4,93.73) ; 40.11,52.32 40.13,52.3 40.13,50.95 C119.1 ; 40.11,52.32 39.88,52.56 C108.2 v1(39.37,53.21) ; 40.11,52.32 C152.2 ; C114.2 C113.2 C112.2 36.32,53.11 36.2,53.23 v1(36.2,53.25) ; C250.2 C253.2 ; C253.2 C256.2 ; 63.37,4.95 63.37,5.59 v2(63.12,5.84) ; U34.2 64.14,18.68 64.64,19.18 64.64,19.69 v1(64.9,19.94) ; C70.2 18.75,99.95 v2(18.77,99.92) ; v2(55.37,66.93) R166.1 ; R166.1 R163.1 R162.1 ; R178.1 67.31,45.72 v1(66.93,46.1) ; C225.1 22.92,26.23 22.77,26.23 22.62,26.38 v1(21.24,26.38) ; v2(71.53,70.82) J15.8 ; v2(45.83,59.71) C94.2 v2(44.58,58.55) ; C211.1 7.62,30.99 v1(7.87,30.73) v1(7.87,29.46) 7.62,29.21 C222.1 ; U38.10 52.84,61.35 52.65,61.16 v2(52.65,61.09) ; R110.1 v2(48.13,87.25) ; v1(45.2,34.27) 44.96,34.27 44.81,34.42 C195.2 ; R96.2 v1(38.42,97.79) ; v2(75.85,91.83) 76.23,91.45 R109.1 ; U31.9 v1(52.2,28.57) ; R99.1 v2(28.19,98.17) ; C221.1 10.92,29.46 11.19,29.73 v1(12.81,29.73) ; 43.05,57.02 44.07,57.02 v1(44.07,57.78) ; v1(44.17,53.31) 44.17,52.35 C109.1 C110.1 C111.1 42.16,52.93 v1(42.57,53.34) ; 29.59,84.07 v2(29.59,84.84) ; C243.2 v1(45.47,18.29) ; C189.2 27.43,37.59 27.14,37.59 26.88,37.34 v1(26.67,37.34) 25.53,36.2 R187.1 ; v2(10.67,14.36) 10.67,12.94 C251.2 9.06,14.07 v2(9.06,14.74) ; v1(12.46,33.77) 13.07,33.77 13.34,34.04 C208.1 ; C220.2 v1(23.8,28.45) 23.84,28.49 24.42,28.49 25.4,29.46 C219.2 ; R162.1 R161.1 R160.1 ; R162.1 v2(57.4,66.93) ; v1(21.23,86.26) 21.23,86.26 21.28,86.23 C76.2 ; C237.2 v2(25.91,21.34) ; v2(67.11,51.89) 66.58,51.89 C102.2 66.58,53.01 v2(67.11,53.01) ; U31.10 53.47,28.41 53.7,28.65 v1(53.93,28.65) ; C264.2 v2(5.33,8.32) ; v2(33.02,67.31) 33.02,66.42 33.29,66.15 C92.2 33.77,66.15 34.04,66.42 v2(34.04,67.31) ; v2(68.74,95.14) R104.1 ; v1(30.48,40.05) 31.2,40.05 C177.2 C182.2 ; C184.2 v2(14.73,38.73) ; R106.1 v2(68.74,93.23) ; R165.1 R164.1 ; R165.1 v2(49.28,66.93) ; R193.1 v1(12.83,30.48) ; v1(40.01,28.74) 40.31,28.45 C218.2 ; v1(32.13,51.69) 31.95,51.51 31.65,51.51 31.24,51.1 C116.2 ; v1(52.7,23.75) 52.2,23.24 U31.8 ; C265.2 C266.2 v2(59.44,8) ; R87.1 v2(24.13,95.63) ; C213.1 10.92,31.64 11.54,32.26 v1(12.83,32.26) ; R185.1 v1(48.13,40.39) ; R223.1 58.17,9.78 v1(58.42,10.03) ; C145.2 v2(16.26,45.97) ; C91.2 65.15,70.87 v2(65.53,71.25) ; v1(37.91,95.38) C74.2 ; J15.10 v2(67.47,69.55) ; R222.1 v1(61.21,10.16) ; C83.2 v1(38.99,78.74) ; C80.2 v2(38.23,85.34) ; C207.2 v1(17.02,35.81) ; R113.1 v2(64.64,85.98) ; C216.2 R195.1 67.94,29.21 v2(67.82,29.34) ; C263.2 v2(6.6,8.69) ; v1(7.11,22.35) 7.11,21.34 6.6,20.83 C235.2 ; C88.2 v1(16.13,69.6) ; R160.1 v2(59.44,66.93) ; C84.2 v2(35.81,76.34) ; U32.3 63.25,24 v2(62.74,23.5) ; C170.2 v1(37.77,42.85) ; C242.2 v1(49.66,18.29) ; R88.1 v2(28.19,99.44) ; C139.2 v1(36.97,46.05) ; C190.2 v2(14.86,37.47) ; v2(15.45,3.3) 15.32,3.3 15.26,3.36 J16.6 ; v2(52.22,35.69) 52.07,35.69 51.55,35.16 C209.2 v2(51.55,33.15) ; 16.89,74.04 v1(16.13,74.04) ; v2(71.88,24.36) 71.53,24 U32.6 70.31,25.83 v2(70.48,26.01) ; v2(7.75,8.26) 7.75,7.37 8.26,6.86 R229.2 ; C269.2 v2(56.01,8) ; C143.1 31.24,44.45 30.63,44.45 30.58,44.5 30.58,44.48 v1(30.57,44.48) ; v2(2.37,8.57) FB13.1 3.68,9.21 v2(2.98,9.91) ; C186.2 v2(69.98,40.39) ; R108.1 v2(68.74,91.2) ; v2(71.63,68.44) 71.61,68.44 71.46,68.28 J15.12 ; C116.2 v1(30.46,50.55) ; C267.2 v2(58.29,8) ; v2(71.37,19.43) 71.12,19.68 70.48,19.68 C239.2 ; U25.4 v2(25.04,96.94) ; R137.1 62.48,72.77 62.74,73.03 v2(62.87,73.03) ; C223.2 34.48,28.32 34.54,28.39 v2(34.58,28.39) ; v2(71.28,63.71) 70.77,63.2 J15.20 ; R221.1 v2(63.63,12.45) 64.39,12.45 64.6,12.66 C252.2 ; R103.1 v2(76.49,96.91) ; C151.2 v1(34.57,44.45) ; R91.2 v1(58.74,97.79) ; U33.2 v1(4.57,23.24) ; C77.2 v2(59.26,85.47) ; C72.2 v1(58.23,95.38) ; R188.1 v1(16,33.27) ; C234.2 50.76,22.59 51.01,22.84 v2(51.01,23.67) ; C175.1 v1(30.48,41.05) ; v1(41.47,95.38) C73.2
  BOTTOM w0.508: R176.1 C125.2 25.6,48.51 v1(25.63,48.49) ; C272.2 v1(29.97,6.35) 29.97,7.6 C260.2 30.73,8.37 v2(30.73,9.4) ; v2(29.33,25.02) 29.33,25.14 29.59,25.4 C227.2 C226.2 ; v2(57.28,20.83) 57.78,20.32 58.04,20.32 ; C178.2 27.05,39.48 v1(27.05,40.64) 27.43,41.02 C171.2 ; C85.2 v2(28.45,76.83) ; v2(29.26,32.22) 29.04,32 C212.2 ; v2(61.72,21.04) C236.2 C238.2 ; v2(28.2,51.56) 28.19,51.56 C121.1 ; C273.2 v2(47.5,3.43) ; C261.2 10.58,8.22 C257.2 10.58,10.07 C254.2 10.43,10.91 C251.2 ; v1(28.57,71.37) 28.7,71.25 C87.2 ; v1(20.52,24.63) 20.57,24.57 C230.2 C229.1 ; v2(23.62,35.56) C194.2 R187.1 ; C179.1 v2(24.88,40.88) ; v1(54.14,52.96) v2(54.86,52.96) ; C205.2 27.43,35.42 C193.2 C189.2 ; v2(72.91,52.58) C97.2 v2(72.91,55.12) ; C123.2 14.61,49.15 U28.3 v1(14.61,52.58) ; C228.2 29.04,23.41 v2(29.04,24.14) ; v1(24.87,43.87) 24.89,43.87 C148.2 ; v2(17.53,17.55) 17.53,17.53 18.07,16.98 J16.9 ; C164.2 27.43,42.55 v1(27.05,42.93) 27.05,43.96 C154.2 ; R242.2 v2(49.85,87.01) ; v1(10.67,18.54) 10.67,17.78 ; 10.67,17.78 C244.2 ; 10.67,17.78 C245.2
  BOTTOM w0.635: R174.1 v1(6.6,55.12)
  BOTTOM w0.889: J11.2 43.02,8.04 ; J11.2 39.99,8.04 ; J11.2 43.02,5.01 ; J11.2 39.99,5.01
  vias: v1(37.82,54.4) v2(16.35,8.35) v2(17.37,11.4) v2(17.37,10.39) v2(17.37,9.37) v2(18.39,11.4) v2(18.39,10.39) v2(18.39,9.37) v2(18.39,8.35) v2(19.4,11.4) v2(19.4,9.37) v2(29.84,66.42) v2(29.84,65.15) v2(30.73,65.79) v2(31.62,66.42) v2(31.62,65.15) v2(37.21,77.6) v2(37.21,76.58) v2(37.21,75.56) v2(37.21,74.55) v2(37.21,25.68) v2(38.23,77.6) v2(38.23,76.58) v2(38.23,75.56) v2(38.23,74.55) v2(39.24,77.6) v2(39.24,76.58) v2(39.24,75.56) v2(39.24,74.55) v2(40.26,77.6) v2(40.26,76.58) v2(40.26,75.56) v2(40.26,74.55) v2(40.65,22.46) v2(41.02,63.5) v2(41.02,62.23) v2(41.91,62.87) v2(42.8,63.5) v2(42.8,62.23) v2(46.74,11.18) v2(47.62,11.18) v2(48.51,11.18) v2(52.45,15.62) v2(53.59,77.6) v2(53.59,76.58) v2(53.59,75.56) v2(53.59,74.55) v2(53.72,15.62) v2(53.72,14.35) v2(53.72,13.08) v2(54.61,77.6) v2(54.61,76.58) v2(54.61,75.56) v2(54.61,74.55) v2(54.99,15.62) v2(54.99,14.35) v2(54.99,13.08) v2(55.63,77.6) v2(55.63,76.58) v2(55.63,75.56) v2(55.63,74.55) v2(56.26,15.62) v2(56.26,14.35) v2(56.26,13.08) v2(56.64,77.6) v2(56.64,76.58) v2(56.64,75.56) v2(56.64,74.55) v2(57.53,15.62) v2(57.53,14.35) v2(57.53,13.08) v2(58.8,15.62) v2(58.8,14.35) v2(58.8,13.08) v2(60.07,15.62) v2(60.07,14.35) v2(60.07,13.08) v2(63.37,6.68) v2(66.67,24.51) v2(67.44,59.94) v2(67.44,35.05) v2(67.56,24.51) v2(68.83,24.26) v2(69.22,35.05) v2(69.22,34.04)
